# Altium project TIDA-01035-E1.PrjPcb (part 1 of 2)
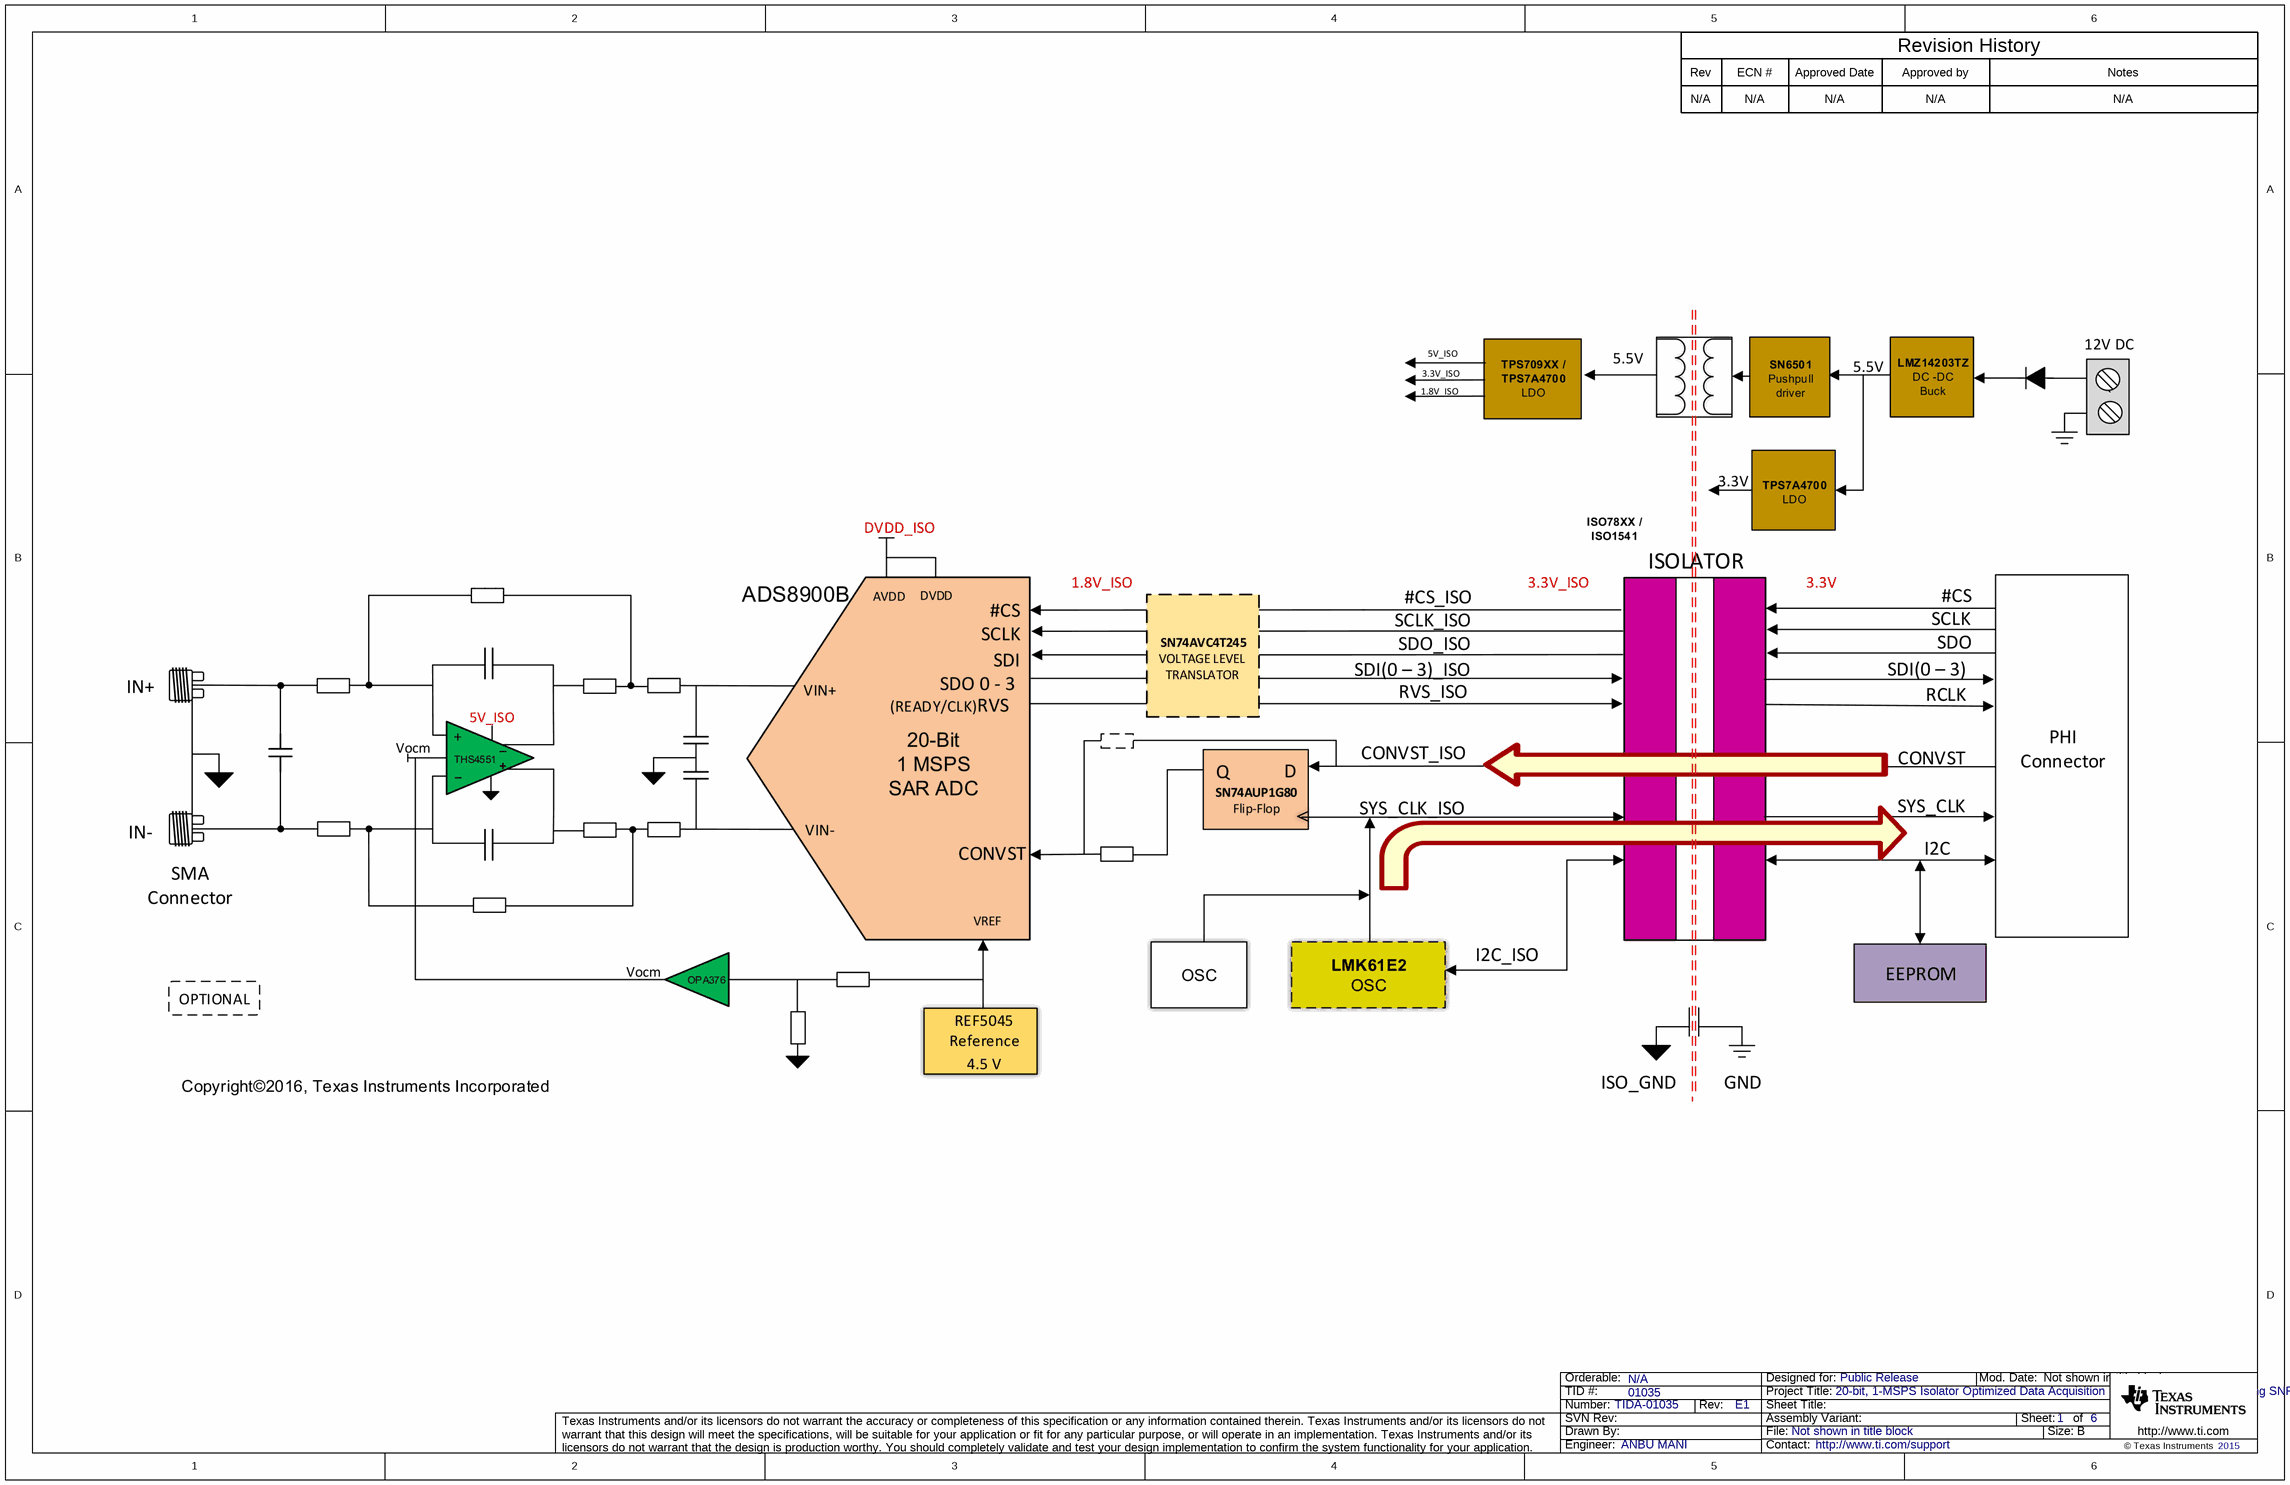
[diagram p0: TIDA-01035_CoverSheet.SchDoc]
CopyrightYear: 2015; EVM_Orderable: N/A; PCB_Layout: Avinash N; PCB_Rev: E1; PRJ_Customer: Public Release; PRJ_Engineer: ANBU MANI; PRJ_Number: TIDA-01035; PRJ_Title: 20-bit, 1-MSPS Isolator Optimized Data Acquisition Reference Design Maximizing SNR and Sample Rate; SCH_Rev: E1; TechSupport: http://www.ti.com/support; TID: 01035
6 sheets, 287 parts. Net scope: flat (ports and power ports of the same name join across sheets).
Board file: TIDA-01035.PcbDoc
Sheets:
  TIDA-01035_CoverSheet.SchDoc
  TIDA-01035_CONNECTOR.SchDoc
  TIDA-01035_POWER_ISOLATION.SchDoc
  TIDA-01035_DATA_ISOLATION.SchDoc
  TIDA-01035_ADC1.SchDoc
  TIDA-01035_Hardware.SchDoc

## Sheet TIDA-01035_CoverSheet.SchDoc
size 431 x 279 mm; Date: Not shown in title block; ApprovedBy: Not shown in title block; CheckedBy: Not shown in title block; Author: Not shown in title block; CompanyName: Not shown in title block; Engineer: Not shown in title block; Organization: Not shown in title block; Address1: Not shown in title block; Address2: Not shown in title block; Address3: Not shown in title block; Address4: Not shown in title block; DocumentNumber: 1; Revision: Use project parameter SCH_Rev; SheetNumber: 1; SheetTotal: 6; PageSetup: Record=PageOptions¦CenterHorizontal=True¦CenterVertical=True¦PrintScale=1.00¦XCorrection=1.00¦YCorrection=1.00¦PrintKind=0¦BorderSize=5000000¦LeftOffset=0¦BottomOffset=0¦Orientation=2¦PaperLength=1000¦PaperWidth=1000¦Scale=100¦PaperSource=15¦PrintQuality=600¦MediaType=1¦DitherType=10¦PrintScaleMode=1¦PaperKind=Letter

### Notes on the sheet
- Rev
- N/A
- ECN #
- Approved Date
- Approved by
- Revision History
- Notes

## Sheet TIDA-01035_CONNECTOR.SchDoc
size 431 x 279 mm; Date: Not shown in title block; ApprovedBy: Not shown in title block; CheckedBy: Not shown in title block; Author: Not shown in title block; CompanyName: Not shown in title block; Engineer: Not shown in title block; Organization: Not shown in title block; Address1: Not shown in title block; Address2: Not shown in title block; Address3: Not shown in title block; Address4: Not shown in title block; DocumentNumber: 1; Revision: Use project parameter SCH_Rev; SheetNumber: 2; SheetTotal: 6; PageSetup: Record=PageOptions¦CenterHorizontal=True¦CenterVertical=True¦PrintScale=1.00¦XCorrection=1.00¦YCorrection=1.00¦PrintKind=0¦BorderSize=5000000¦LeftOffset=0¦BottomOffset=0¦Orientation=2¦PaperLength=1000¦PaperWidth=1000¦Scale=100¦PaperSource=15¦PrintQuality=600¦MediaType=1¦DitherType=10¦PaperKind=Letter¦PrintScaleMode=1
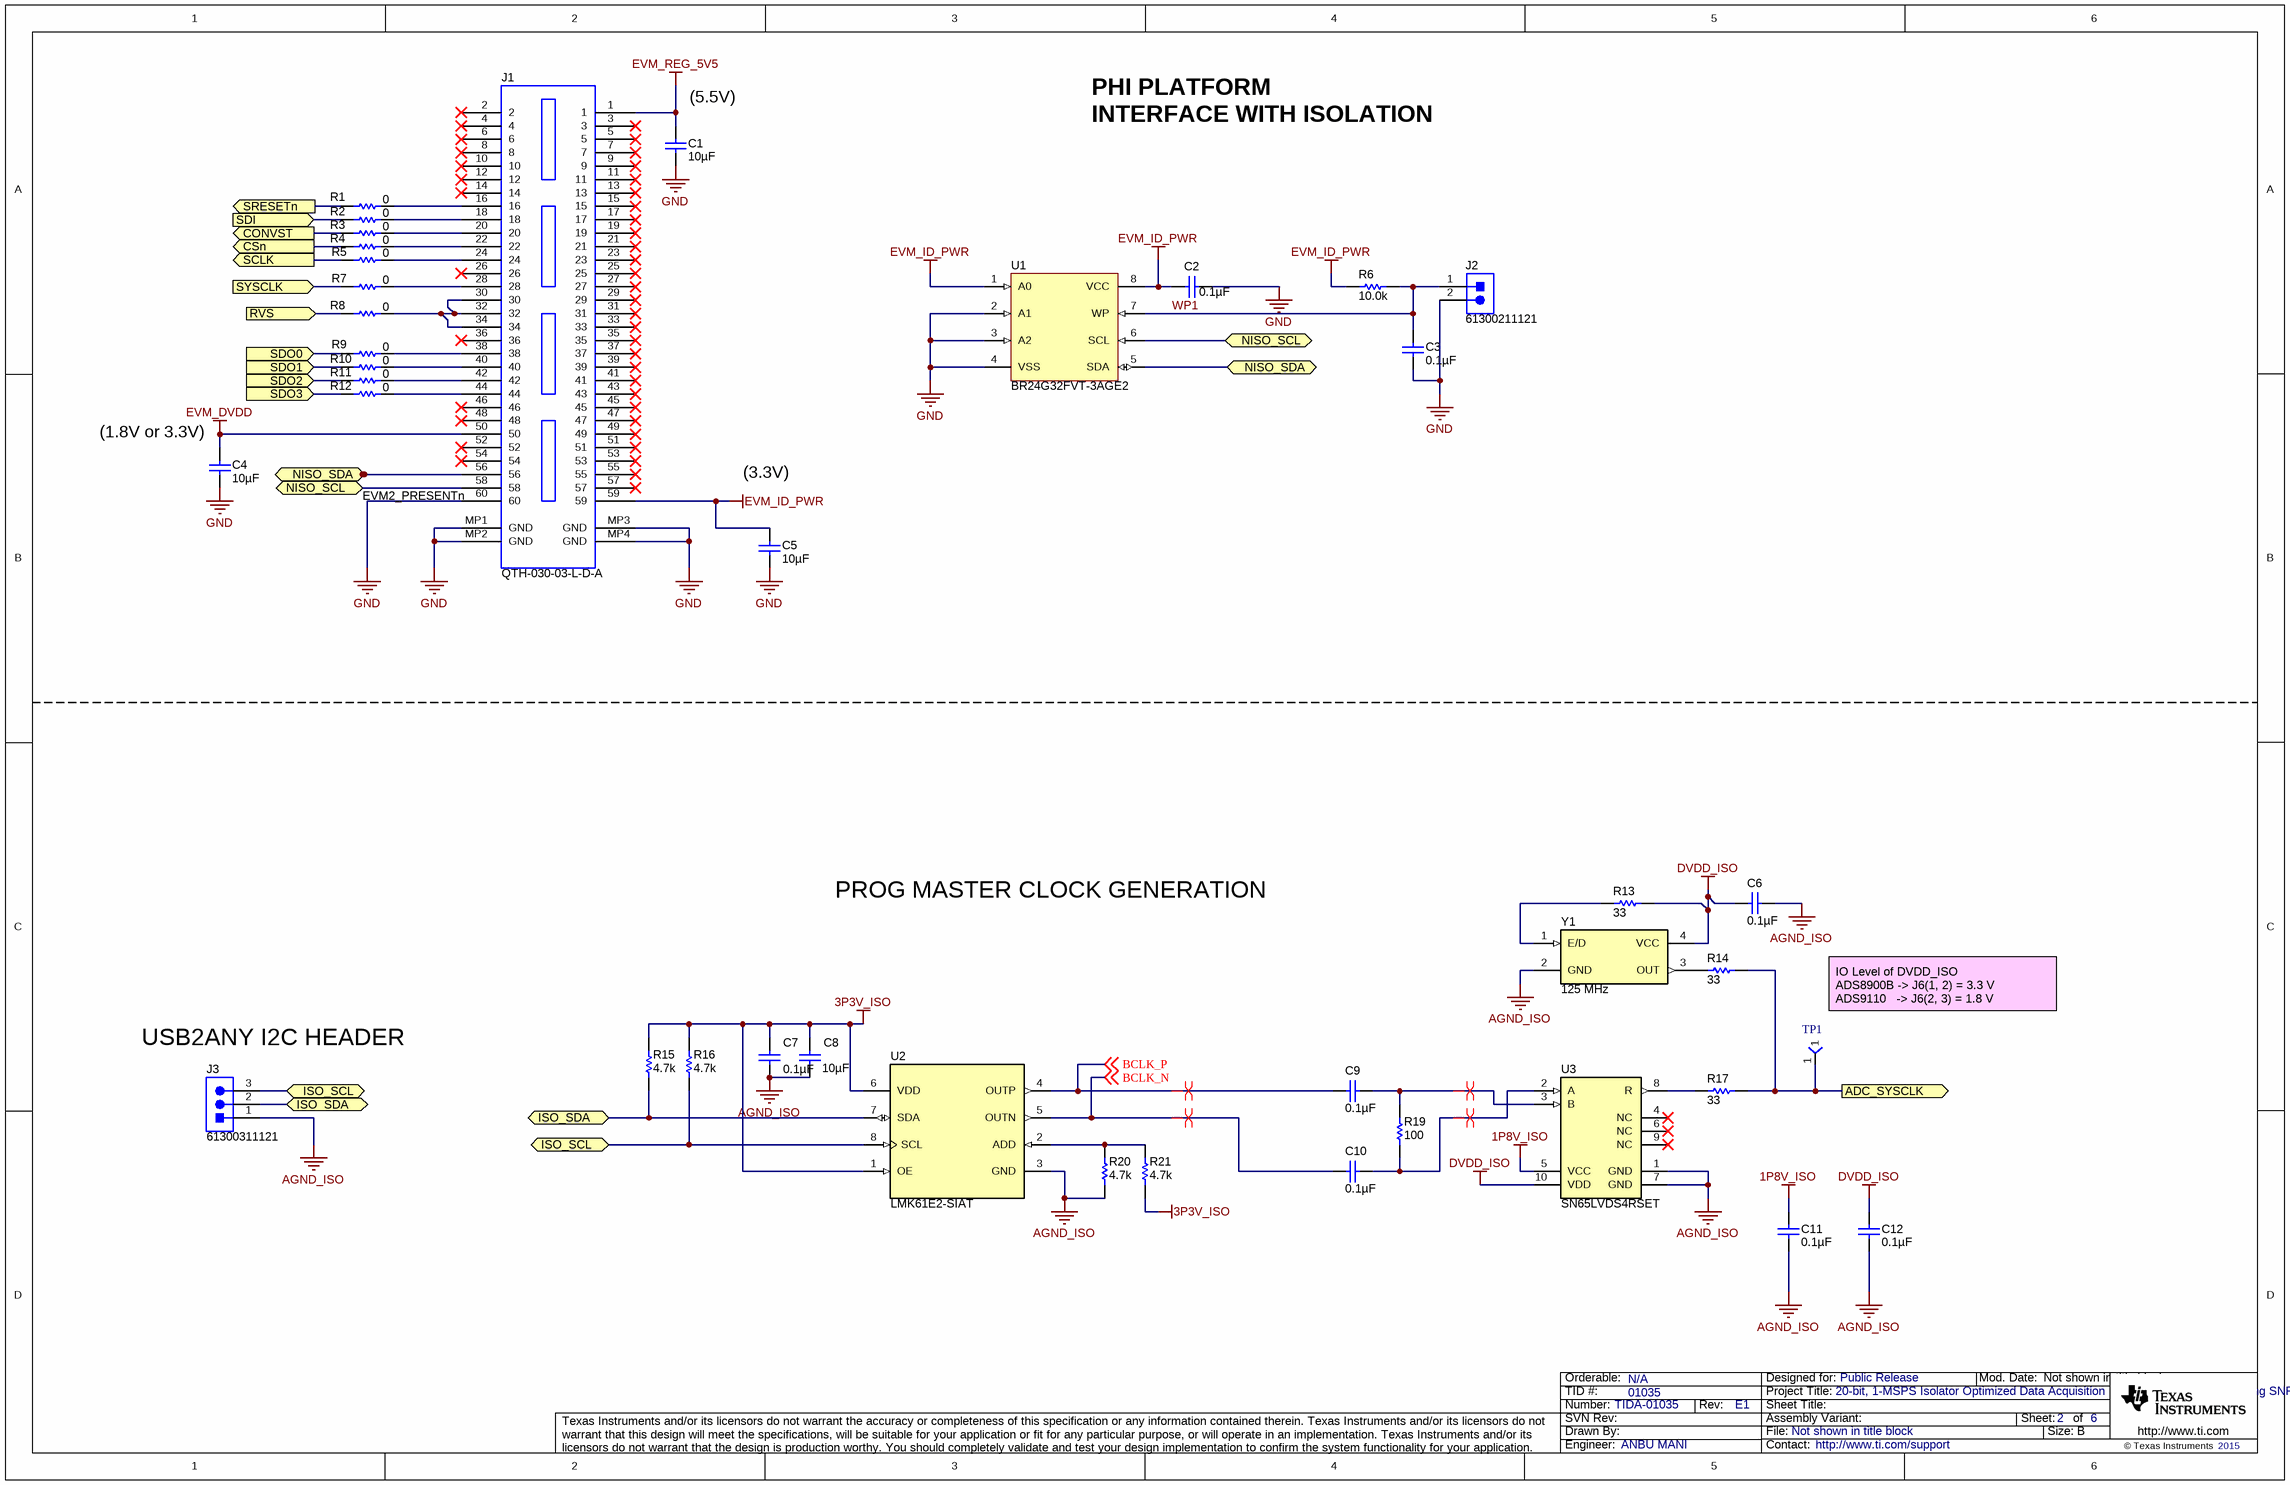
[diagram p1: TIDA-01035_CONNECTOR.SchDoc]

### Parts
C1  ValueDisplayed: 10µF  [0805_HV]  (hidden comment: GRM21BR71A106KE51L)
C2  ValueDisplayed: 0.1µF  [0402]  (hidden comment: GRM155R71C104KA88D)
C3  ValueDisplayed: 0.1µF  [0402]  (hidden comment: GRM155R71C104KA88D)
C4  ValueDisplayed: 10µF  [0805_HV]  (hidden comment: GRM21BR71A106KE51L)
C5  ValueDisplayed: 10µF  [0805_HV]  (hidden comment: GRM21BR71A106KE51L)
C6  ValueDisplayed: 0.1µF  [0402]  (hidden comment: GRM155R71C104KA88D)
C7  ValueDisplayed: 0.1µF  [0603]  (hidden comment: C0603C104J3RACTU)
C8  ValueDisplayed: 10µF  [0603_120]  (hidden comment: ZRB18AD71A106KE01L)
C9  ValueDisplayed: 0.1µF  [0402]  (hidden comment: GRM155R61E104KA87D)
C10  ValueDisplayed: 0.1µF  [0402]  (hidden comment: GRM155R61E104KA87D)
C11  ValueDisplayed: 0.1µF  [0402]  (hidden comment: GRM155R71C104KA88D)
C12  ValueDisplayed: 0.1µF  [0402]  (hidden comment: GRM155R71C104KA88D)
J1  QTH-030-03-L-D-A  [Samtec_QTH-030-01-x-D-A]
J2  61300211121  [WURTH_61300211121]
J3  61300311121  [WURTH_61300311121]
R1  ValueDisplayed: 0  [0402]  (hidden comment: ERJ-2GE0R00X)
R2  ValueDisplayed: 0  [0402]  (hidden comment: ERJ-2GE0R00X)
R3  ValueDisplayed: 0  [0402]  (hidden comment: ERJ-2GE0R00X)
R4  ValueDisplayed: 0  [0402]  (hidden comment: ERJ-2GE0R00X)
R5  ValueDisplayed: 0  [0402]  (hidden comment: ERJ-2GE0R00X)
R6  ValueDisplayed: 10.0k  [0603]  (hidden comment: CRCW060310K0FKEA)
R7  ValueDisplayed: 0  [0402]  (hidden comment: ERJ-2GE0R00X)
R8  ValueDisplayed: 0  [0402]  (hidden comment: ERJ-2GE0R00X)
R9  ValueDisplayed: 0  [0402]  (hidden comment: ERJ-2GE0R00X)
R10  ValueDisplayed: 0  [0402]  (hidden comment: ERJ-2GE0R00X)
R11  ValueDisplayed: 0  [0402]  (hidden comment: ERJ-2GE0R00X)
R12  ValueDisplayed: 0  [0402]  (hidden comment: ERJ-2GE0R00X)
R13  ValueDisplayed: 33  [0402]  (hidden comment: CRCW040233R0JNED)
R14  ValueDisplayed: 33  [0402]  (hidden comment: CRCW040233R0JNED)
R15  ValueDisplayed: 4.7k  [0402]  (hidden comment: CRCW04024K70JNED)
R16  ValueDisplayed: 4.7k  [0402]  (hidden comment: CRCW04024K70JNED)
R17  ValueDisplayed: 33  [0402]  (hidden comment: CRCW040233R0JNED)
R19  ValueDisplayed: 100  [0402]  (hidden comment: RC0402FR-07100RL)
R20  ValueDisplayed: 4.7k  [0402]  (hidden comment: CRCW04024K70JNED)
R21  ValueDisplayed: 4.7k  [0402]  (hidden comment: CRCW04024K70JNED)
TP1  TP-025-SMT  [TP_25MIL-SMT]  (value not drawn)
U1  BR24G32FVT-3AGE2  [TSOP65P640X120-8N]
U2  LMK61E2-SIAT  [SIA0008B]
U3  SN65LVDS4RSET  [RSE0010A]
Y1  Frequency: 125 MHz  [TXC_AU]  (hidden comment: ASTMLPE-125.000MHZ-LJ-E-T)

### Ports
ADC_SYSCLK (out), CONVST (out), CSn (out), ISO_SCL (bidir), ISO_SDA (bidir), NISO_SCL (bidir), NISO_SDA (bidir), RVS (in), SCLK (out), SDI (in), SDO0 (in), SDO1 (in), SDO2 (in), SDO3 (in), SRESETn (out), SYSCLK (in)

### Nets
1P8V_ISO: C11.1 U3.5(VCC)
3P3V_ISO: C7.1 C8.1 R15.2 R16.2 R21.1 U2.1(OE) U2.6(VDD)
AGND_ISO: C6.2 C7.2 C8.2 C11.2 C12.2 J3.1 R20.1 U2.3(GND) U3.1(GND) U3.7(GND) Y1.2(GND)
DVDD_ISO: C6.1 C12.1 R13.2 U3.10(VDD) Y1.4(VCC)
EVM_DVDD: C4.1 J1.50
EVM_ID_PWR: C2.2 C5.1 J1.59 R6.2 U1.1(A0) U1.8(VCC)
EVM_REG_5V5: C1.1 J1.1
GND: C1.2 C2.1 C3.1 C4.2 C5.2 J1.60 J1.MP1(GND) J1.MP2(GND) J1.MP3(GND) J1.MP4(GND) J2.2 U1.2(A1) U1.3(A2) U1.4(VSS)
ADC_SYSCLK: R14.2 R17.2 TP1.1 ; port ADC_SYSCLK
BCLK_N: C10.1 U2.5(OUTN) ; off-sheet BCLK_N
BCLK_P: C9.1 U2.4(OUTP) ; off-sheet BCLK_P
CONVST: R3.1 ; port CONVST
CSn: R4.1 ; port CSn
ISO_SCL: J3.3 R16.1 U2.8(SCL) ; port ISO_SCL
ISO_SDA: J3.2 R15.1 U2.7(SDA) ; port ISO_SDA
NISO_SCL: J1.58 U1.6(SCL) ; port NISO_SCL
NISO_SDA: J1.56 U1.5(SDA) ; port NISO_SDA
RVS: R8.1 ; port RVS
SCLK: R5.1 ; port SCLK
SDI: R2.1 ; port SDI
SDO0: R9.1 ; port SDO0
SDO1: R10.1 ; port SDO1
SDO2: R11.1 ; port SDO2
SDO3: R12.1 ; port SDO3
SRESETn: R1.1 ; port SRESETn
SYSCLK: R7.1 ; port SYSCLK
WP1: C3.2 J2.1 R6.1 U1.7(WP)
NetC9_2: C9.2 R19.2 U3.3(B)
NetC10_2: C10.2 R19.1 U3.2(A)
NetJ1_16: J1.16 R1.2
NetJ1_18: J1.18 R2.2
NetJ1_20: J1.20 R3.2
NetJ1_22: J1.22 R4.2
NetJ1_24: J1.24 R5.2
NetJ1_28: J1.28 R7.2
NetJ1_30: J1.30 J1.32 J1.34 R8.2
NetJ1_38: J1.38 R9.2
NetJ1_40: J1.40 R10.2
NetJ1_42: J1.42 R11.2
NetJ1_44: J1.44 R12.2
NetR13_1: R13.1 Y1.1(E/D)
NetR14_1: R14.1 Y1.3(OUT)
NetR17_1: R17.1 U3.8(R)
NetR20_2: R20.2 R21.2 U2.2(ADD)

Not connected (* = marked no-connect by the designer): J1 2* 3* 4* 5* 6* 7* 8* 9* 10* 11* 12* 13* 14* 15* 17* 19* 21* 23* 25* 26* 27* 29* 31* 33* 35* 36* 37* 39* 41* 43* 45* 46* 47* 48* 49* 51* 52* 53* 54* 55* 57*; U3 4(NC)* 6(NC)* 9(NC)*

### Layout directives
differential pair: BCLK_N, BCLK_P, NetC9_2, NetC10_2

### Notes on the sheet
- (near C1) (5.5V)
- PHI PLATFORM
  INTERFACE WITH ISOLATION
- (near C4) (1.8V or 3.3V)
- (near J1) EVM2_PRESENTn
- (3.3V)
- PROG MASTER CLOCK GENERATION
- (near J3) USB2ANY I2C HEADER
- (near TP1) IO Level of DVDD_ISO
  ADS8900B -> J6(1, 2) = 3.3 V
  ADS9110   -> J6(2, 3) = 1.8 V

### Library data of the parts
C1 C4 C5 = GRM21BR71A106KE51L: CAP, CERM, 10 µF, 10 V, +/- 10%, X7R, 0805; Manufacturer: MuRata; Polarized: N; CompType: Capacitor; Value: 10uF; U/M: EA; Cap_F: 0.00001; Tolerance_%: 10; ESR_ohm: 0.003; Value1: 0.003 ohm; Value2: 10V; TaMin_C: -55; TaMax_C: 125; Cap_Case: 0805; AEC Category: Q200
C2 C3 C6 C11 C12 = GRM155R71C104KA88D: CAP, CERM, 0.1 µF, 16 V, +/- 10%, X7R, 0402; Manufacturer: MuRata; Polarized: N; CompType: Capacitor; Value: 0.1uF; U/M: EA; Cap_F: 0.0000001; Tolerance_%: 10; Value1: Unknown; VDC_V: 16; Value2: 16V; TaMin_C: -55; TaMax_C: 125
C7 = C0603C104J3RACTU: CAP, CERM, 0.1 µF, 25 V, +/- 5%, X7R, 0603; Manufacturer: Kemet; Polarized: N; CompType: Capacitor; Value: 0.1uF; U/M: EA; Cap_F: 0.0000001; Tolerance_%: 5; Value1: Unknown; VDC_V: 25; Value2: 25V; TaMin_C: -55; TaMax_C: 125
C8 = ZRB18AD71A106KE01L: CAP, CERM, 10 µF, 10 V, +/- 10%, X7T, 0603; Manufacturer: MuRata; Polarized: N; CompType: Capacitor; Value: 10uF; U/M: EA; Cap_F: 0.00001; Tolerance_%: 10; Value1: Unknown; Value2: 10V; TaMin_C: -55; TaMax_C: 125; Cap_Case: 0603; AEC Category: Q200
C9 C10 = GRM155R61E104KA87D: CAP, CERM, 0.1 µF, 25 V, +/- 10%, X5R, 0402; Manufacturer: MuRata; Polarized: N; CompType: Capacitor; Value: 0.1uF; U/M: EA; Cap_F: 0.0000001; Tolerance_%: 10; Value1: Unknown; VDC_V: 25; Value2: 25V; TaMin_C: -55; TaMax_C: 85; AEC Category: Q200
J1 = QTH-030-01-L-D-A: Header(Shrouded), 19.7mil, 30x2, Gold, SMT; Manufacturer: Samtec; SymbolCreator: Altium; U/M: EA
J2 = 61300211121: Header, 2.54 mm, 2x1, Gold, TH; Manufacturer: Wurth Elektronik eiSos; SymbolCreator: a0412235; U/M: EA
J3 = 61300311121: Header, 2.54 mm, 3x1, Gold, TH; Manufacturer: Wurth Elektronik eiSos; SymbolCreator: a0799628; U/M: EA
R1-R5 R7-R12 = ERJ-2GE0R00X: RES, 0, 5%, 0.063 W, 0402; Manufacturer: Panasonic; CompType: Resistor; Value: 0; Value_Code: 0000; Tolerance_%: 5; Power_W: 0.063; Value2: 0.063W; VDC_V: 50; TempCo: 600 ppm/C; EIA_Code: E24; U/M: EA; AEC Category: Q200
R6 = CRCW060310K0FKEA: RES, 10.0 k, 1%, 0.1 W, 0603; Manufacturer: Vishay-Dale; CompType: Resistor; Value: 10.0k; Res_ohm: 10000; Value_Code: 10k0; Tolerance_%: 1; Power_W: 0.1; Value2: 0.1W; VDC_V: 75; TempCo: 100 ppm/C; EIA_Code: E96; U/M: EA
R13 R14 R17 = CRCW040233R0JNED: RES, 33, 5%, 0.063 W, 0402; Manufacturer: Vishay-Dale; CompType: Resistor; Value: 33; Value_Code: 33R0; Tolerance_%: 5; Power_W: 0.063; Value2: 0.063W; VDC_V: 50; TempCo: 200 ppm/C; EIA_Code: E24; U/M: EA; AEC Category: Q200
R15 R16 R20 R21 = CRCW04024K70JNED: RES, 4.7 k, 5%, 0.063 W, 0402; Manufacturer: Vishay-Dale; CompType: Resistor; Value: 4.7k; Res_ohm: 4700; Value_Code: 4k70; Tolerance_%: 5; Power_W: 0.063; Value2: 0.063W; VDC_V: 50; TempCo: 200 ppm/C; EIA_Code: E24; U/M: EA; AEC Category: Q200
R19 = RC0402FR-07100RL: RES, 100, 1%, 0.063 W, 0402; Manufacturer: Yageo America; CompType: Resistor; Value: 100; Value_Code: 100R; Tolerance_%: 1; Power_W: 0.063; Value2: 0.063W; VDC_V: 50; TempCo: 100 ppm/C; EIA_Code: E96; U/M: EA; AEC Category: Q200; AEC Qualified: N; SizeArea_mm2: 0.5; SizeZ_mm: 0.6
TP1 = TP-025-SMT: Test Point, O.025"; Manufacturer: STD; Value: STD
U1 = BR24G32FVT-3AGE2: I2C BUS EEPROM (2-Wire), TSSOP-B8; Manufacturer: Rohm; SymbolCreator: a0411947
U2 = LMK61E2-SIAR: Ultra-Low Jitter Programmable Oscillator with Internal EEPROM, SIA0008B; Manufacturer: Texas Instruments; SymbolCreator: Altium; CompType: IC; U/M: EA
U3 = SN65LVDS4RSET: 500 Mbps High-Speed Differential Line Driver / Receivers with LVDS Input and LVTTL / LVCMOS Output, 1 Rx, -40 to +85 degC, 10-pin UQFN (RSE), Green (RoHS & no Sb/Br); Manufacturer: Texas Instruments; Alternate PartNumber: Equivalent; ESD HBM(kV): 2; Function: Transceiver; No. of Rx: 1; No. of Tx: 0; Output Signal: LVTTL, LVCMOS; Signaling Rate(Mbps): 500; SubFamily: LVDS PHY (<800Mbps)
Y1 = AU-40.000MDE-T: OSC, 125 MHz, 3.3V, SMD; Manufacturer: ABRACON; SymbolCreator: a0411947; CompType: Oscillator; U/M: EA; TaMin_C: -40; TaMax_C: 85; Frequency Stability: ±50ppm

## Sheet TIDA-01035_POWER_ISOLATION.SchDoc: LDO's Isolated & Non Isolated
size 431 x 279 mm; Date: Not shown in title block; ApprovedBy: Not shown in title block; CheckedBy: Not shown in title block; Author: Not shown in title block; CompanyName: Not shown in title block; DrawnBy: Anbu Mani; Engineer: Not shown in title block; Organization: Not shown in title block; Address1: Not shown in title block; Address2: Not shown in title block; Address3: Not shown in title block; Address4: Not shown in title block; DocumentNumber: 1; Revision: Use project parameter SCH_Rev; SheetNumber: 3; SheetTotal: 6; PageSetup: Record=PageOptions¦CenterHorizontal=True¦CenterVertical=True¦PrintScale=1.00¦XCorrection=1.00¦YCorrection=1.00¦PrintKind=0¦BorderSize=5000000¦LeftOffset=0¦BottomOffset=0¦Orientation=2¦PaperLength=1000¦PaperWidth=1000¦Scale=100¦PaperSource=15¦PrintQuality=600¦MediaType=1¦DitherType=10¦PaperKind=Letter¦PrintScaleMode=1
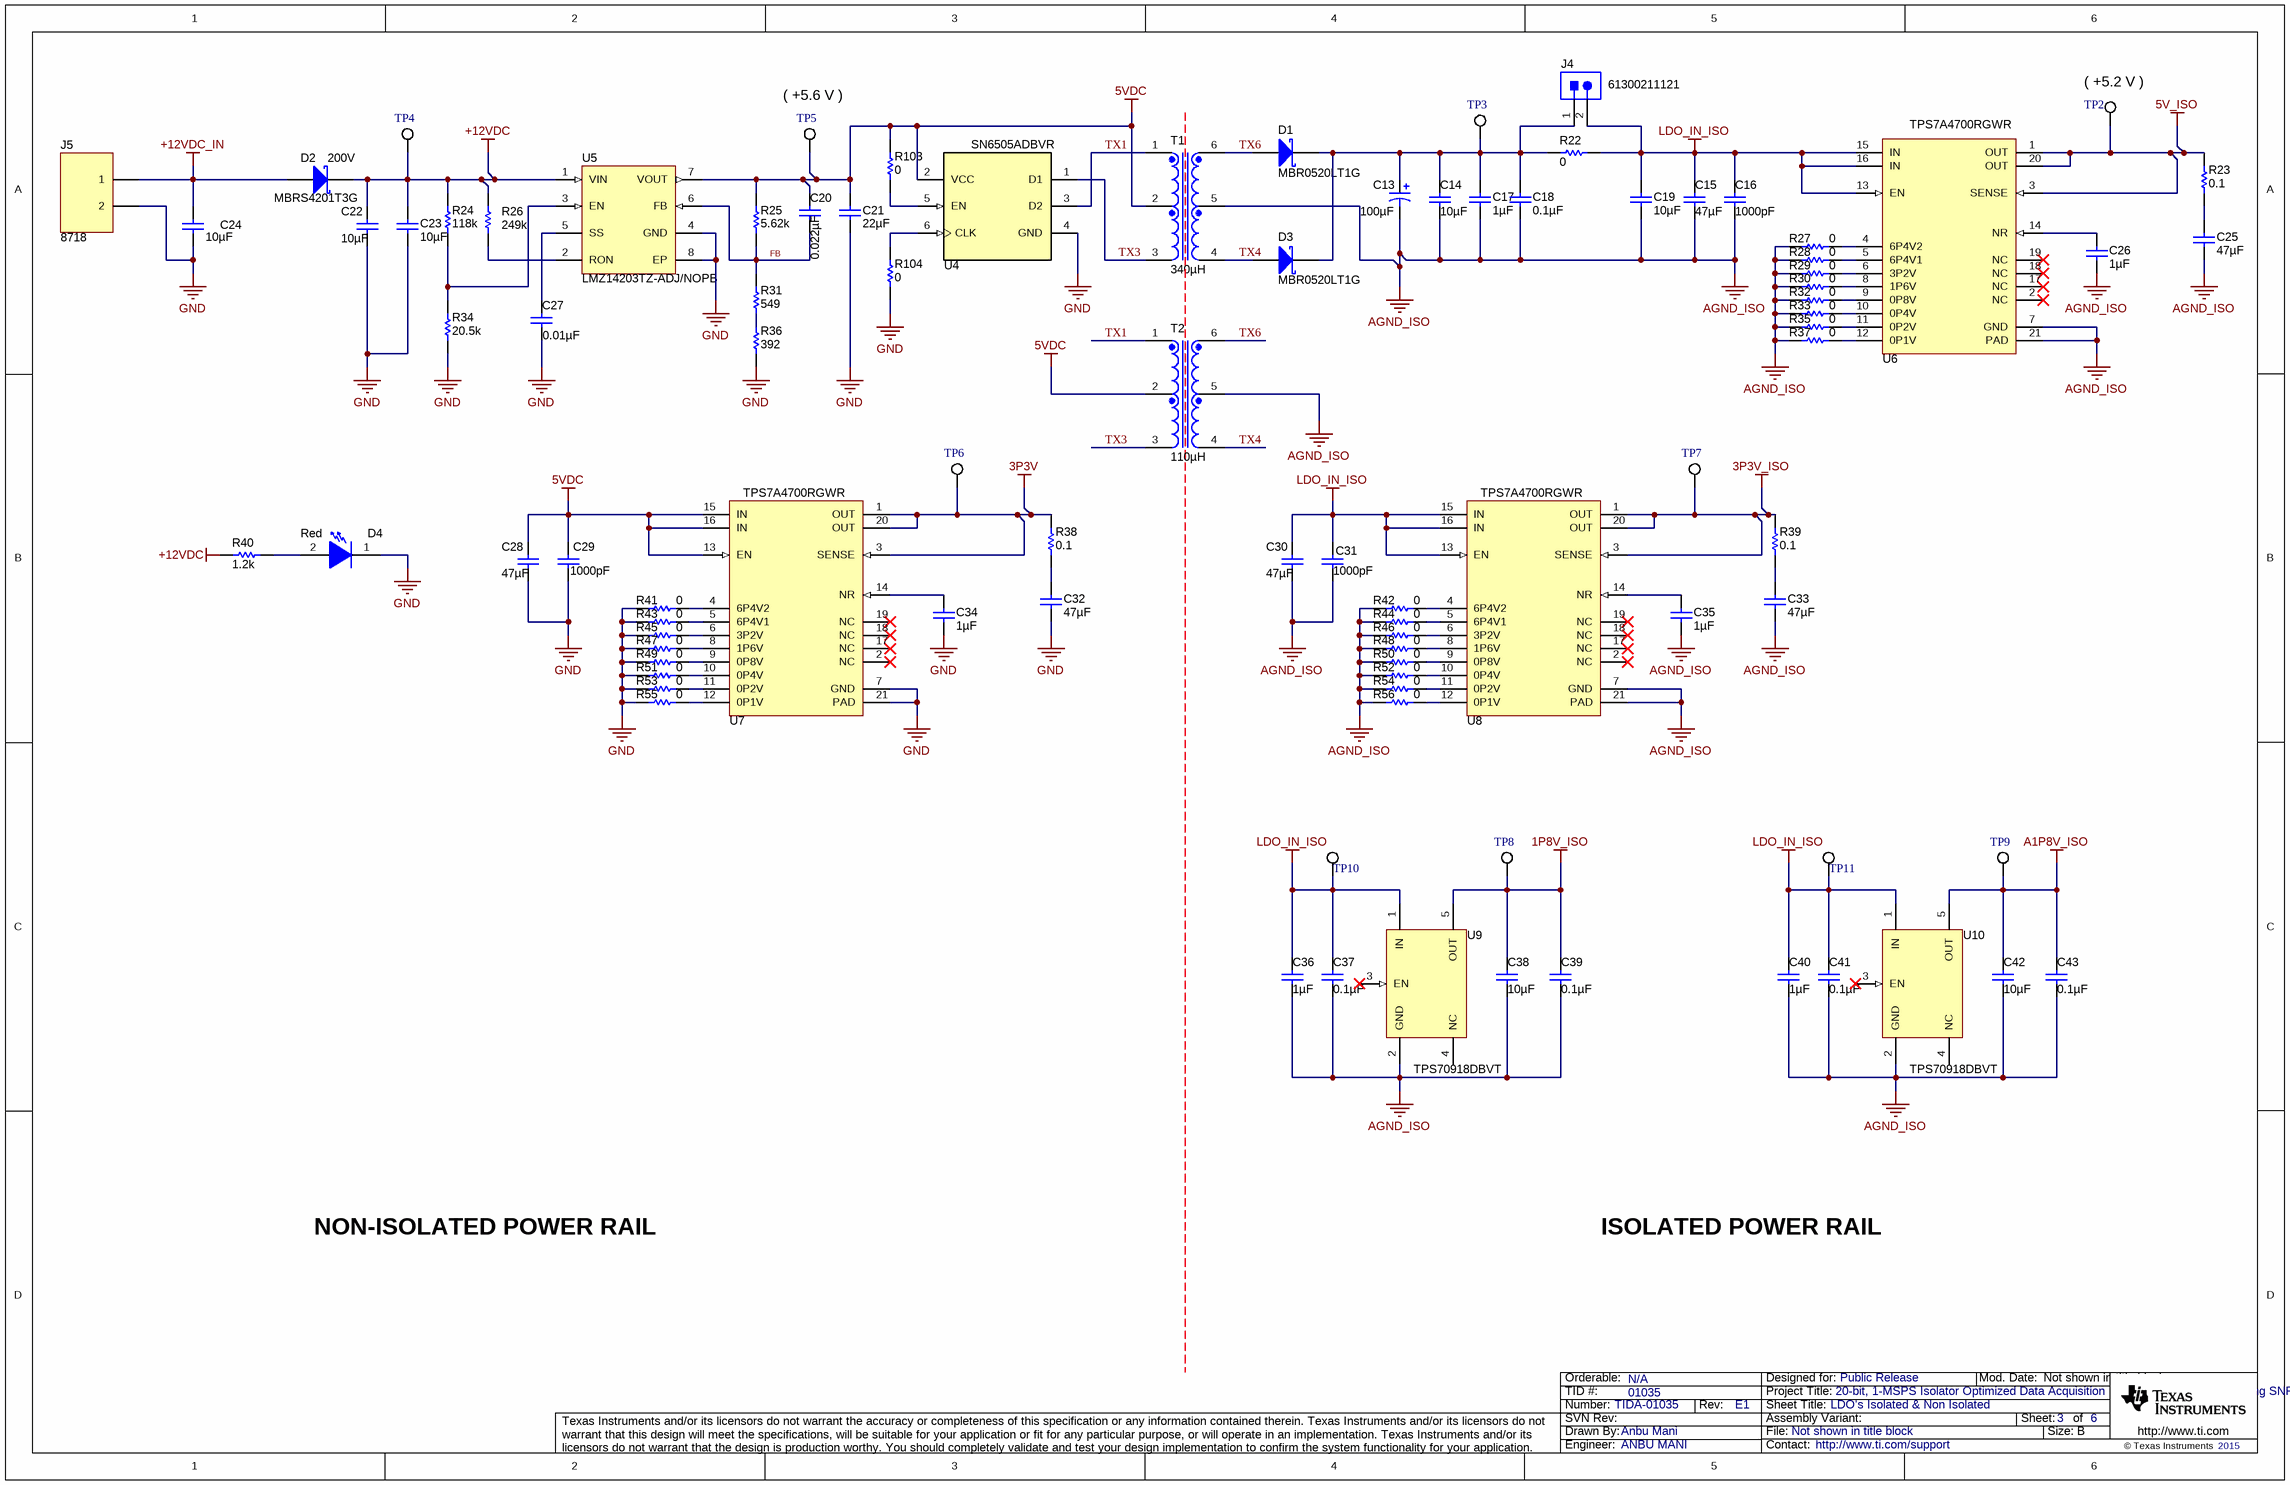
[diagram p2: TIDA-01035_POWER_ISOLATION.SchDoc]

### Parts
C13  ValueDisplayed: 100µF  [7343-43]  (hidden comment: TPME107K020R0035)
C14  ValueDisplayed: 10µF  [1206_190]  (hidden comment: C3216X7R1E106M160AE)
C15  ValueDisplayed: 47µF  [1206_190]  (hidden comment: C3216X5R1E476M160AC)
C16  ValueDisplayed: 1000pF  [0603]  (hidden comment: GRM1885C1H102FA01J)
C17  ValueDisplayed: 1µF  [0603]  (hidden comment: GRM188R71E105KA12D)
C18  ValueDisplayed: 0.1µF  [0402]  (hidden comment: GRM155R71C104KA88D)
C19  ValueDisplayed: 10µF  [0805_HV]  (hidden comment: GRM21BR71A106KE51L)
C20  ValueDisplayed: 0.022µF  [0805_HV]  (hidden comment: 08055C223KAT2A)
C21  ValueDisplayed: 22µF  [1210]  (hidden comment: C3225X5R1A226M230AA)
C22  ValueDisplayed: 10µF  [1210_280]  (hidden comment: C1210C106K5RACTU)
C23  ValueDisplayed: 10µF  [1210_280]  (hidden comment: C1210C106K5RACTU)
C24  ValueDisplayed: 10µF  [1206_190]  (hidden comment: C3216X7R1E106M160AE)
C25  ValueDisplayed: 47µF  [1206_190]  (hidden comment: C3216X5R1E476M160AC)
C26  ValueDisplayed: 1µF  [0603]  (hidden comment: GRM188R71E105KA12D)
C27  ValueDisplayed: 0.01µF  [0603]  (hidden comment: C0603C103J5RACTU)
C28  ValueDisplayed: 47µF  [1206_190]  (hidden comment: C3216X5R1E476M160AC)
C29  ValueDisplayed: 1000pF  [0603]  (hidden comment: GRM1885C1H102FA01J)
C30  ValueDisplayed: 47µF  [1206_190]  (hidden comment: C3216X5R1E476M160AC)
C31  ValueDisplayed: 1000pF  [0603]  (hidden comment: GRM1885C1H102FA01J)
C32  ValueDisplayed: 47µF  [1206_190]  (hidden comment: C3216X5R1E476M160AC)
C33  ValueDisplayed: 47µF  [1206_190]  (hidden comment: C3216X5R1E476M160AC)
C34  ValueDisplayed: 1µF  [0603]  (hidden comment: GRM188R71E105KA12D)
C35  ValueDisplayed: 1µF  [0603]  (hidden comment: GRM188R71E105KA12D)
C36  ValueDisplayed: 1µF  [0805]  (hidden comment: 08055C105KAT2A)
C37  ValueDisplayed: 0.1µF  [0603]  (hidden comment: C0603C104K5RACTU)
C38  ValueDisplayed: 10µF  [0805]  (hidden comment: 0805YD106MAT2A)
C39  ValueDisplayed: 0.1µF  [0603]  (hidden comment: C0603C104K5RACTU)
C40  ValueDisplayed: 1µF  [0805]  (hidden comment: 08055C105KAT2A)
C41  ValueDisplayed: 0.1µF  [0603]  (hidden comment: C0603C104K5RACTU)
C42  ValueDisplayed: 10µF  [0805]  (hidden comment: 0805YD106MAT2A)
C43  ValueDisplayed: 0.1µF  [0603]  (hidden comment: C0603C104K5RACTU)
D1  MBR0520LT1G  [SOD-123]
D2  value 200V  [SMC]  (hidden comment: MBRS4201T3G)
D3  MBR0520LT1G  [SOD-123]
D4  value Red  [WL-SMCW_RED]  (hidden comment: 150060RS75000)
J4  61300211121  [WURTH_61300211121]
J5  8718  [691213510002]
R22  ValueDisplayed: 0  [1206]  (hidden comment: CRCW12060000Z0EA)
R23  ValueDisplayed: 0.1  [0603]  (hidden comment: ERJ-3RSFR10V)
R24  ValueDisplayed: 118k  [0805_HV]  (hidden comment: ERJ-6ENF1183V)
R25  ValueDisplayed: 5.62k  [0805_HV]  (hidden comment: RC0805FR-075K62L)
R26  value 249k  [0805_HV]  (hidden comment: CRCW0805249KFKEA)
R27  ValueDisplayed: 0  [0402]  (hidden comment: ERJ-2GE0R00X)
R28  ValueDisplayed: 0  [0402]  (hidden comment: ERJ-2GE0R00X)
R29  ValueDisplayed: 0  [0402]  (hidden comment: ERJ-2GE0R00X)
R30  ValueDisplayed: 0  [0402]  (hidden comment: ERJ-2GE0R00X)
R31  ValueDisplayed: 549  [0805_HV]  (hidden comment: RR1220P-5490-D-M)
R32  ValueDisplayed: 0  [0402]  (hidden comment: ERJ-2GE0R00X)
R33  ValueDisplayed: 0  [0402]  (hidden comment: ERJ-2GE0R00X)
R34  ValueDisplayed: 20.5k  [0805_HV]  (hidden comment: CRCW080520K5FKEA)
R35  ValueDisplayed: 0  [0402]  (hidden comment: ERJ-2GE0R00X)
R36  ValueDisplayed: 392  [0805_HV]  (hidden comment: RR1220P-3920-D-M)
R37  ValueDisplayed: 0  [0402]  (hidden comment: ERJ-2GE0R00X)
R38  ValueDisplayed: 0.1  [0603]  (hidden comment: ERJ-3RSFR10V)
R39  ValueDisplayed: 0.1  [0603]  (hidden comment: ERJ-3RSFR10V)
R40  ValueDisplayed: 1.2k  [0603]  (hidden comment: CRCW06031K20JNEA)
R41  ValueDisplayed: 0  [0402]  (hidden comment: ERJ-2GE0R00X)
R42  ValueDisplayed: 0  [0402]  (hidden comment: ERJ-2GE0R00X)
R43  ValueDisplayed: 0  [0402]  (hidden comment: ERJ-2GE0R00X)
R44  ValueDisplayed: 0  [0402]  (hidden comment: ERJ-2GE0R00X)
R45  ValueDisplayed: 0  [0402]  (hidden comment: ERJ-2GE0R00X)
R46  ValueDisplayed: 0  [0402]  (hidden comment: ERJ-2GE0R00X)
R47  ValueDisplayed: 0  [0402]  (hidden comment: ERJ-2GE0R00X)
R48  ValueDisplayed: 0  [0402]  (hidden comment: ERJ-2GE0R00X)
R49  ValueDisplayed: 0  [0402]  (hidden comment: ERJ-2GE0R00X)
R50  ValueDisplayed: 0  [0402]  (hidden comment: ERJ-2GE0R00X)
R51  ValueDisplayed: 0  [0402]  (hidden comment: ERJ-2GE0R00X)
R52  ValueDisplayed: 0  [0402]  (hidden comment: ERJ-2GE0R00X)
R53  ValueDisplayed: 0  [0402]  (hidden comment: ERJ-2GE0R00X)
R54  ValueDisplayed: 0  [0402]  (hidden comment: ERJ-2GE0R00X)
R55  ValueDisplayed: 0  [0402]  (hidden comment: ERJ-2GE0R00X)
R56  ValueDisplayed: 0  [0402]  (hidden comment: ERJ-2GE0R00X)
R103  ValueDisplayed: 0  [0603]  (hidden comment: CRCW06030000Z0EA)
R104  ValueDisplayed: 0  [0603]  (hidden comment: CRCW06030000Z0EA)
T1  ValueDisplayed: 340µH  [Wurth_750313638]  (hidden comment: 750313734)
T2  ValueDisplayed: 110µH  [Wurth_750315240]  (hidden comment: 750315240)
TP2  5015  [Testpoint_Keystone_Miniature]  (value not drawn)
TP3  5015  [Testpoint_Keystone_Miniature]  (value not drawn)
TP4  5015  [Testpoint_Keystone_Miniature]  (value not drawn)
TP5  5015  [Testpoint_Keystone_Miniature]  (value not drawn)
TP6  5015  [Testpoint_Keystone_Miniature]  (value not drawn)
TP7  5015  [Testpoint_Keystone_Miniature]  (value not drawn)
TP8  5015  [Testpoint_Keystone_Miniature]  (value not drawn)
TP9  5015  [Testpoint_Keystone_Miniature]  (value not drawn)
TP10  5015  [Testpoint_Keystone_Miniature]  (value not drawn)
TP11  5015  [Testpoint_Keystone_Miniature]  (value not drawn)
U4  SN6505ADBVR  [DBV0006A_N]
U5  LMZ14203TZ-ADJ/NOPB  [TZA07A_V]
U6  TPS7A4700RGWR  [RGW0020A]
U7  TPS7A4700RGWR  [RGW0020A]
U8  TPS7A4700RGWR  [RGW0020A]
U9  TPS70918DBVT  [DBV0005A_N]
U10  TPS70918DBVT  [DBV0005A_N]

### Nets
1P8V_ISO: C38.1 C39.1 TP8.1 U9.5(OUT)
3P3V: R38.2 TP6.1 U7.1(OUT) U7.3(SENSE) U7.20(OUT)
3P3V_ISO: R39.2 TP7.1 U8.1(OUT) U8.3(SENSE) U8.20(OUT)
5V_ISO: R23.2 TP2.1 U6.1(OUT) U6.3(SENSE) U6.20(OUT)
5VDC: C20.1 C21.1 C28.1 C29.1 R25.2 R103.2 T1.2 T2.2 TP5.1 U4.2(VCC) U5.7(VOUT) U7.13(EN) U7.15(IN) U7.16(IN)
+12VDC: C22.1 C23.1 D2.1(K) R24.2 R26.2 R40.2 TP4.1 U5.1(VIN)
+12VDC_IN: C24.1 D2.2(A) J5.1
A1P8V_ISO: C42.1 C43.1 TP9.1 U10.5(OUT)
AGND_ISO: C13.2(-) C14.2 C15.2 C16.2 C17.2 C18.1 C19.2 C25.2 C26.1 C30.2 C31.2 C33.2 C35.1 C36.2 C37.2 C38.2 C39.2 C40.2 C41.2 C42.2 C43.2 R27.1 R28.1 R29.1 R30.1 R32.1 R33.1 R35.1 R37.1 R42.1 R44.1 R46.1 R48.1 R50.1 R52.1 R54.1 R56.1 T1.5 T2.5 U6.7(GND) U6.21(PAD) U8.7(GND) U8.21(PAD) U9.2(GND) U10.2(GND)
GND: C21.2 C22.2 C23.2 C24.2 C27.2 C28.2 C29.2 C32.2 C34.1 D4.1(K) J5.2 R34.1 R36.1 R41.1 R43.1 R45.1 R47.1 R49.1 R51.1 R53.1 R55.1 R104.1 U4.4(GND) U5.4(GND) U5.8(EP) U7.7(GND) U7.21(PAD)
LDO_IN_ISO: C15.1 C16.1 C19.1 C30.1 C31.1 C36.1 C37.1 C40.1 C41.1 J4.2 R22.2 TP10.1 TP11.1 U6.13(EN) U6.15(IN) U6.16(IN) U8.13(EN) U8.15(IN) U8.16(IN) U9.1(IN) U10.1(IN)
FB: C20.2 R25.1 R31.2 U5.6(FB)
TX1: T1.1 T2.1 U4.3(D2)
TX3: T1.3 T2.3 U4.1(D1)
TX4: D3.2(A) T1.4 T2.4
TX6: D1.2(A) T1.6 T2.6
NetC13_1: C13.1(+) C14.1 C17.1 C18.2 D1.1(K) D3.1(K) J4.1 R22.1 TP3.1
NetC25_1: C25.1 R23.1
NetC26_2: C26.2 U6.14(NR)
NetC27_1: C27.1 U5.5(SS)
NetC32_1: C32.1 R38.1
NetC33_1: C33.1 R39.1
NetC34_2: C34.2 U7.14(NR)
NetC35_2: C35.2 U8.14(NR)
NetD4_2: D4.2(A) R40.1
NetR24_1: R24.1 R34.2 U5.3(EN)
NetR26_1: R26.1 U5.2(RON)
NetR27_2: R27.2 U6.4(6P4V2)
NetR28_2: R28.2 U6.5(6P4V1)
NetR29_2: R29.2 U6.6(3P2V)
NetR30_2: R30.2 U6.8(1P6V)
NetR31_1: R31.1 R36.2
NetR32_2: R32.2 U6.9(0P8V)
NetR33_2: R33.2 U6.10(0P4V)
NetR35_2: R35.2 U6.11(0P2V)
NetR37_2: R37.2 U6.12(0P1V)
NetR41_2: R41.2 U7.4(6P4V2)
NetR42_2: R42.2 U8.4(6P4V2)
NetR43_2: R43.2 U7.5(6P4V1)
NetR44_2: R44.2 U8.5(6P4V1)
NetR45_2: R45.2 U7.6(3P2V)
NetR46_2: R46.2 U8.6(3P2V)
NetR47_2: R47.2 U7.8(1P6V)
NetR48_2: R48.2 U8.8(1P6V)
NetR49_2: R49.2 U7.9(0P8V)
NetR50_2: R50.2 U8.9(0P8V)
NetR51_2: R51.2 U7.10(0P4V)
NetR52_2: R52.2 U8.10(0P4V)
NetR53_2: R53.2 U7.11(0P2V)
NetR54_2: R54.2 U8.11(0P2V)
NetR55_2: R55.2 U7.12(0P1V)
NetR56_2: R56.2 U8.12(0P1V)
NetR103_1: R103.1 U4.5(EN)
NetR104_2: R104.2 U4.6(CLK)

Not connected (* = marked no-connect by the designer): U6 2(NC)* 17(NC)* 18(NC)* 19(NC)*; U7 2(NC)* 17(NC)* 18(NC)* 19(NC)*; U8 2(NC)* 17(NC)* 18(NC)* 19(NC)*; U9 3(EN)* 4(NC); U10 3(EN)* 4(NC)

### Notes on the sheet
- (near TP2) ( +5.2 V )
- (near TP5) ( +5.6 V )
- NON-ISOLATED POWER RAIL
- ISOLATED POWER RAIL

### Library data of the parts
C13 = 293D107X9020E2TE3: 100µF ±10% Molded Tantalum Capacitors 20V 2917 (7343 Metric) 35 mOhm; Manufacturer: AVX Corporation; Polarized: Y; Value: 100uF; U/M: EA; Cap_F: 0.0001; Tolerance_%: 10; Value1: 0.5 ohm; VDC_V: 20; ESR_ohm: 0.5; IRMS_A: 0.57; TaMin_C: -55; TaMax_C: 125; Cap_Case: E; AEC Category: Q200
C14 C24 = C3216X7R1E106M160AE: CAP, CERM, 10 µF, 25 V, +/- 20%, X7R, 1206_190; Manufacturer: TDK; Polarized: N; CompType: Capacitor; Value: 10uF; U/M: EA; Cap_F: 0.00001; Tolerance_%: 20; Value1: Unknown; VDC_V: 25; Value2: 25V; TaMin_C: -55; TaMax_C: 125; Cap_Case: 1206; AEC Category: Q200
C15 C25 C28 C30 C32 C33 = C3216X5R1E476M160AC: CAP, CERM, 47 µF, 25 V, +/- 20%, X5R, 1206_190; Manufacturer: TDK; Polarized: N; CompType: Capacitor; Value: 47uF; U/M: EA; Cap_F: 0.000047; Tolerance_%: 20; Value1: Unknown; VDC_V: 25; Value2: 25V; TaMin_C: -55; TaMax_C: 85; Cap_Case: 1206; AEC Category: Q200
C16 C29 C31 = GRM1885C1H102FA01J: CAP, CERM, 1000 pF, 50 V, +/- 1%, C0G/NP0, 0603; Manufacturer: MuRata; Polarized: N; CompType: Capacitor; Value: 1000pF; U/M: EA; Cap_F: 0.000000001; Tolerance_%: 1; Value1: Unknown; VDC_V: 50; Value2: 50V; TaMin_C: -55; TaMax_C: 125; AEC Category: Q200
C17 = GRM188R71E105KA12D: CAP, CERM, 1 µF, 25 V, +/- 10%, X7R, 0603; Manufacturer: MuRata; Polarized: N; CompType: Capacitor; Value: 1uF; U/M: EA; Cap_F: 0.000001; Tolerance_%: 10; Value1: Unknown; VDC_V: 25; Value2: 25V; TaMin_C: -55; TaMax_C: 125
C18 = GRM155R71C104KA88D: as C2 on sheet TIDA-01035_CONNECTOR
C19 = GRM21BR71A106KE51L: as C1 on sheet TIDA-01035_CONNECTOR
C20 = 08055C223KAT2A: CAP, CERM, 0.022uF, 50V, +/-10%, X7R, 0805; Manufacturer: AVX; Polarized: N; CompType: Capacitor; U/M: EA; Cap_F: 0.000000022; Tolerance_%: 10; ESR_Ohm: 0.052; Value1: 0.052 ohm; VDC_V: 50; TaMin_C: -55; TaMax_C: 125; Cap_Case: 0805
C21 = C3225X5R1A226M: CAP, CERM, 22uF, 10V, +/-20%, X5R, 1210; Manufacturer: TDK; Polarized: N; CompType: Capacitor; U/M: EA; Cap_F: 0.000022; Tolerance_%: 20; ESR_Ohm: 0.002; Value1: 0.002 ohm; VDC_V: 10; IRMS_A: 3.2; TaMin_C: -55; TaMax_C: 85
C22 C23 = UMK325AB7106KM-T: 10µF ±10% 50V Ceramic Capacitor X7R 1210 (3225 Metric); Manufacturer: Kemet; Polarized: N; Value: 10uF; U/M: EA; Cap_F: 0.00001; Tolerance_%: 10; Value1: Unknown; VDC_V: 50; TaMin_C: -55; TaMax_C: 125; Cap_Case: 1210; AEC Category: Q200
C26 C34 C35 = GRM188R71E105KA12D: CAP, CERM, 1 µF, 25 V, +/- 10%, X7R, 0603; Manufacturer: MuRata; Polarized: N; CompType: Capacitor; Value: 1uF; U/M: EA; Cap_F: 0.000001; Tolerance_%: 10; Value1: Unknown; VDC_V: 25; Value2: 25V; TaMin_C: -55; TaMax_C: 125; AEC Category: Q200
C27 = C0603C103J5RACTU: CAP, CERM, 0.01uF, 50V, +/-5%, X7R, 0603; Manufacturer: Kemet; Polarized: N; CompType: Capacitor; U/M: EA; Cap_F: 0.00000001; Tolerance_%: 5; Value1: Unknown; VDC_V: 50; TaMin_C: -55; TaMax_C: 125
C36 C40 = 08055C105KAT2A: CAP, CERM, 1uF, 50V, +/-10%, X7R, 0805; Manufacturer: AVX; Polarized: N; CompType: Capacitor; U/M: EA; Cap_F: 0.000001; Tolerance_%: 10; Value1: Unknown; VDC_V: 50; TaMin_C: -55; TaMax_C: 125
C37 C39 C41 C43 = C0603C104K5RACTU: CAP, CERM, 0.1uF, 50V, +/-10%, X7R, 0603; Manufacturer: Kemet; Polarized: N; CompType: Capacitor; U/M: EA; Cap_F: 0.0000001; Tolerance_%: 10; Value1: Unknown; VDC_V: 50; TaMin_C: -55; TaMax_C: 125
C38 C42 = 0805YD106MAT2A: CAP, CERM, 10uF, 16V, +/-20%, X5R, 0805; Manufacturer: AVX; Polarized: N; CompType: Capacitor; U/M: EA; Cap_F: 0.00001; Tolerance_%: 20; Value1: Unknown; VDC_V: 16; TaMin_C: -55; TaMax_C: 85
D1 D3 = MBR0520LT1G: Diode, Schottky, 20 V, 0.5 A, SOD-123; Manufacturer: ON Semiconductor; U/M: EA; Vf_V: 0.385; Value: 20V; Value1: 0.5A; Value2: 0.385V; Io_A: 0.5; Vr_V: 20; TJmax_C: 125; RJC_CperW: 150; AEC Category: Q101
D2 = MBRS4201T3G: Diode, Schottky, 200V, 4A, SMC; Manufacturer: ON Semiconductor; Io_A: 4
D4 = 150060RS75000: LED, Red, SMD; Manufacturer: Wurth Elektronik; Type: AlInGaP; Vf_V: 2; Value2: 2V; Io_A: 0.03; Vr_V: 5; Tjmax_C: 85; Power_TotalModule: 0.072; Value1: 0.072W; Angle: 140; U/M: EA
J4 = 61300211121: as J2 on sheet TIDA-01035_CONNECTOR
J5 = 691213510002: 2 Position Wire to Board Terminal Block Horizontal with Board 0.197" (5.00mm) Through Hole; Manufacturer: Keystone Electronics; ComponentLink1 Description: Manufacturer; ComponentLink2 Description: Datasheet; NoPins: 2
R22 = CRCW12060000Z0EA: RES, 0, 5%, 0.25 W, 1206; Manufacturer: Vishay-Dale; CompType: Resistor; Value: 0; Value_Code: 0000; Tolerance_%: 5; Power_W: 0.25; Value2: 0.25W; VDC_V: 200; TempCo: 200 ppm/C; EIA_Code: E24; U/M: EA; AEC Category: Q200
R23 R38 R39 = ERJ-3RSFR10V: RES, 0.1, 1%, 0.1 W, 0603; Manufacturer: Panasonic; CompType: Resistor; Value: 0.1; Value_Code: R100; Tolerance_%: 1; Value2: 0.1W; TempCo: 300 ppm/C; EIA_Code: E96; U/M: EA; AEC Category: Q200
R24 = ERJ-6ENF1183V: RES, 118 k, 1%, 0.125 W, 0805; Manufacturer: Panasonic; CompType: Resistor; Value: 118k; Res_ohm: 118000; Tolerance_%: 1; Power_W: 0.125; Value2: 0.125W; TempCo: 100 ppm/C; EIA_Code: E96; U/M: EA; SizeArea_mm2: 2.5; SizeX_mm: 2; SizeY_mm: 1.25; SizeZ_mm: 1.45; AEC Category: Q200
R25 = RT0805BRD075K62L: RES, 5.62 k, 0.1%, 0.125 W, 0805; Manufacturer: Yageo America; CompType: Resistor; Value: 5.62k; Res_ohm: 5620; Value_Code: 5k62; Tolerance_%: 0.1; Power_W: 0.125; Value2: 0.125W; VDC_V: 150; TempCo: 25 ppm/C; EIA_Code: E192; U/M: EA; AEC Category: Q200
R26 = CRCW0805249KFKEA: RES, 249k ohm, 1%, 0.125W, 0805; Manufacturer: Vishay-Dale; CompType: Resistor; Res_ohm: 249000; Tolerance_%: 1; Power_W: 0.125; VDC_V: 150; TempCo: 100 ppm/C; EIA_Code: E96; U/M: EA
R27-R30 R32 R33 R35 R37 R41-R56 = ERJ-2GE0R00X: as R1 on sheet TIDA-01035_CONNECTOR
R31 = RR1220P-5490-D-M: RES, 549, 0.5%, 0.1 W, 0805; Manufacturer: Susumu Co Ltd; CompType: Resistor; Value: 549; Value_Code: 549R; Tolerance_%: 0.5; Power_W: 0.1; Value2: 0.1W; VDC_V: 100; TempCo: 25 ppm/C; EIA_Code: E192; U/M: EA; AEC Category: Q200; SizeArea_mm2: 2.5; SizeX_mm: 2; SizeY_mm: 1.25; SizeZ_mm: 1.45
R34 = CRCW080520K5FKEA: RES, 20.5 k, 1%, 0.125 W, 0805; Manufacturer: Vishay-Dale; CompType: Resistor; Value: 20.5k; Res_ohm: 20500; Value_Code: 20k5; Tolerance_%: 1; Power_W: 0.125; Value2: 0.125W; VDC_V: 150; TempCo: 100 ppm/C; EIA_Code: E96; U/M: EA; AEC Category: Q200
R36 = RR1220P-3920-D-M: RES, 392, 0.5%, 0.1 W, 0805; Manufacturer: Susumu Co Ltd; CompType: Resistor; Value: 392; Value_Code: 392R; Tolerance_%: 0.5; Power_W: 0.1; Value2: 0.1W; VDC_V: 100; TempCo: 25 ppm/C; EIA_Code: E192; U/M: EA; AEC Category: Q200; SizeArea_mm2: 2.5; SizeX_mm: 2; SizeY_mm: 1.25; SizeZ_mm: 1.45
R40 = CRCW06031K20JNEA: RES, 1.2 k, 5%, 0.1 W, 0603; Manufacturer: Vishay-Dale; CompType: Resistor; Value: 1.2k; Res_ohm: 1200; Value_Code: 1k20; Tolerance_%: 5; Power_W: 0.1; Value2: 0.1W; VDC_V: 75; TempCo: 200 ppm/C; EIA_Code: E24; U/M: EA; AEC Category: Q200
R103 R104 = CRCW06030000Z0EA: RES, 0, 5%, 0.1 W, 0603; Manufacturer: Vishay-Dale; CompType: Resistor; Value: 0; Value_Code: 0000; Tolerance_%: 5; Power_W: 0.1; Value2: 0.1W; VDC_V: 75; TempCo: 200 ppm/C; EIA_Code: E24; U/M: EA; AEC Category: Q200
T1 = 750313734: Transformer, 340 uH, TH; Manufacturer: Wurth Elektronik; SymbolCreator: Altium; Value: 340uH; Lp: 340; DCR_ohm: 0.419
T2 = 750315240: Transformer, 110 uH, SMT; Manufacturer: Wurth Elektronik; SymbolCreator: Altium; Value: 110uH; Lp: 110; DCR_ohm: 0.15
TP2-TP11 = 5015: Test Point, Miniature, SMT; Manufacturer: Keystone; CompType: Test Point Loop
U4 = SN6505ADBVR: LOW-NOISE 1A TRANSFORMER DRIVERS FOR ISOLATED POWER SUPPLIES, DBV0006A; Alternate PartNumber: SN6505ADBVT; Manufacturer: Texas Instruments; SymbolCreator: Altium; CompType: IC; U/M: EA
U5 = LMZ14203TZ-ADJ/NOPB: 3A SIMPLE SWITCHER® Power Module with 42V Maximum Input Voltage, 7-pin TO-PMOD, Pb-Free; Manufacturer: Texas Instruments; PackageTopMarking: NSUZXYTTE#*LMZ14203*TZ-ADJ; PowerWise: Y
U6-U8 = TPS7A4700RGWR: 36-V, 1-A, 4.17-μVRMS, RF LDO Voltage Regulator, RGW0020A; Alternate PartNumber: TPS7A4700RGWT; Manufacturer: Texas Instruments; SymbolCreator: a0412235; CompType: IC; U/M: EA
U9 U10 = TPS70933DBVT: IC REG LDO 1.8V 0.15A SOT23-5; Alternate Manufacturer: None; Manufacturer: Texas Instruments; SymbolCreator: a0411947; U/M: EA

## Sheet TIDA-01035_DATA_ISOLATION.SchDoc
size 431 x 279 mm; Date: Not shown in title block; ApprovedBy: Not shown in title block; CheckedBy: Not shown in title block; Author: Not shown in title block; CompanyName: Not shown in title block; Engineer: Not shown in title block; Organization: Not shown in title block; Address1: Not shown in title block; Address2: Not shown in title block; Address3: Not shown in title block; Address4: Not shown in title block; DocumentNumber: 1; Revision: Use project parameter SCH_Rev; SheetNumber: 4; SheetTotal: 6; PageSetup: Record=PageOptions¦CenterHorizontal=True¦CenterVertical=True¦PrintScale=1.00¦XCorrection=1.00¦YCorrection=1.00¦PrintKind=0¦BorderSize=5000000¦LeftOffset=0¦BottomOffset=0¦Orientation=2¦PaperLength=1000¦PaperWidth=1000¦Scale=100¦PaperSource=15¦PrintQuality=600¦MediaType=1¦DitherType=10¦PaperKind=Letter¦PrintScaleMode=1
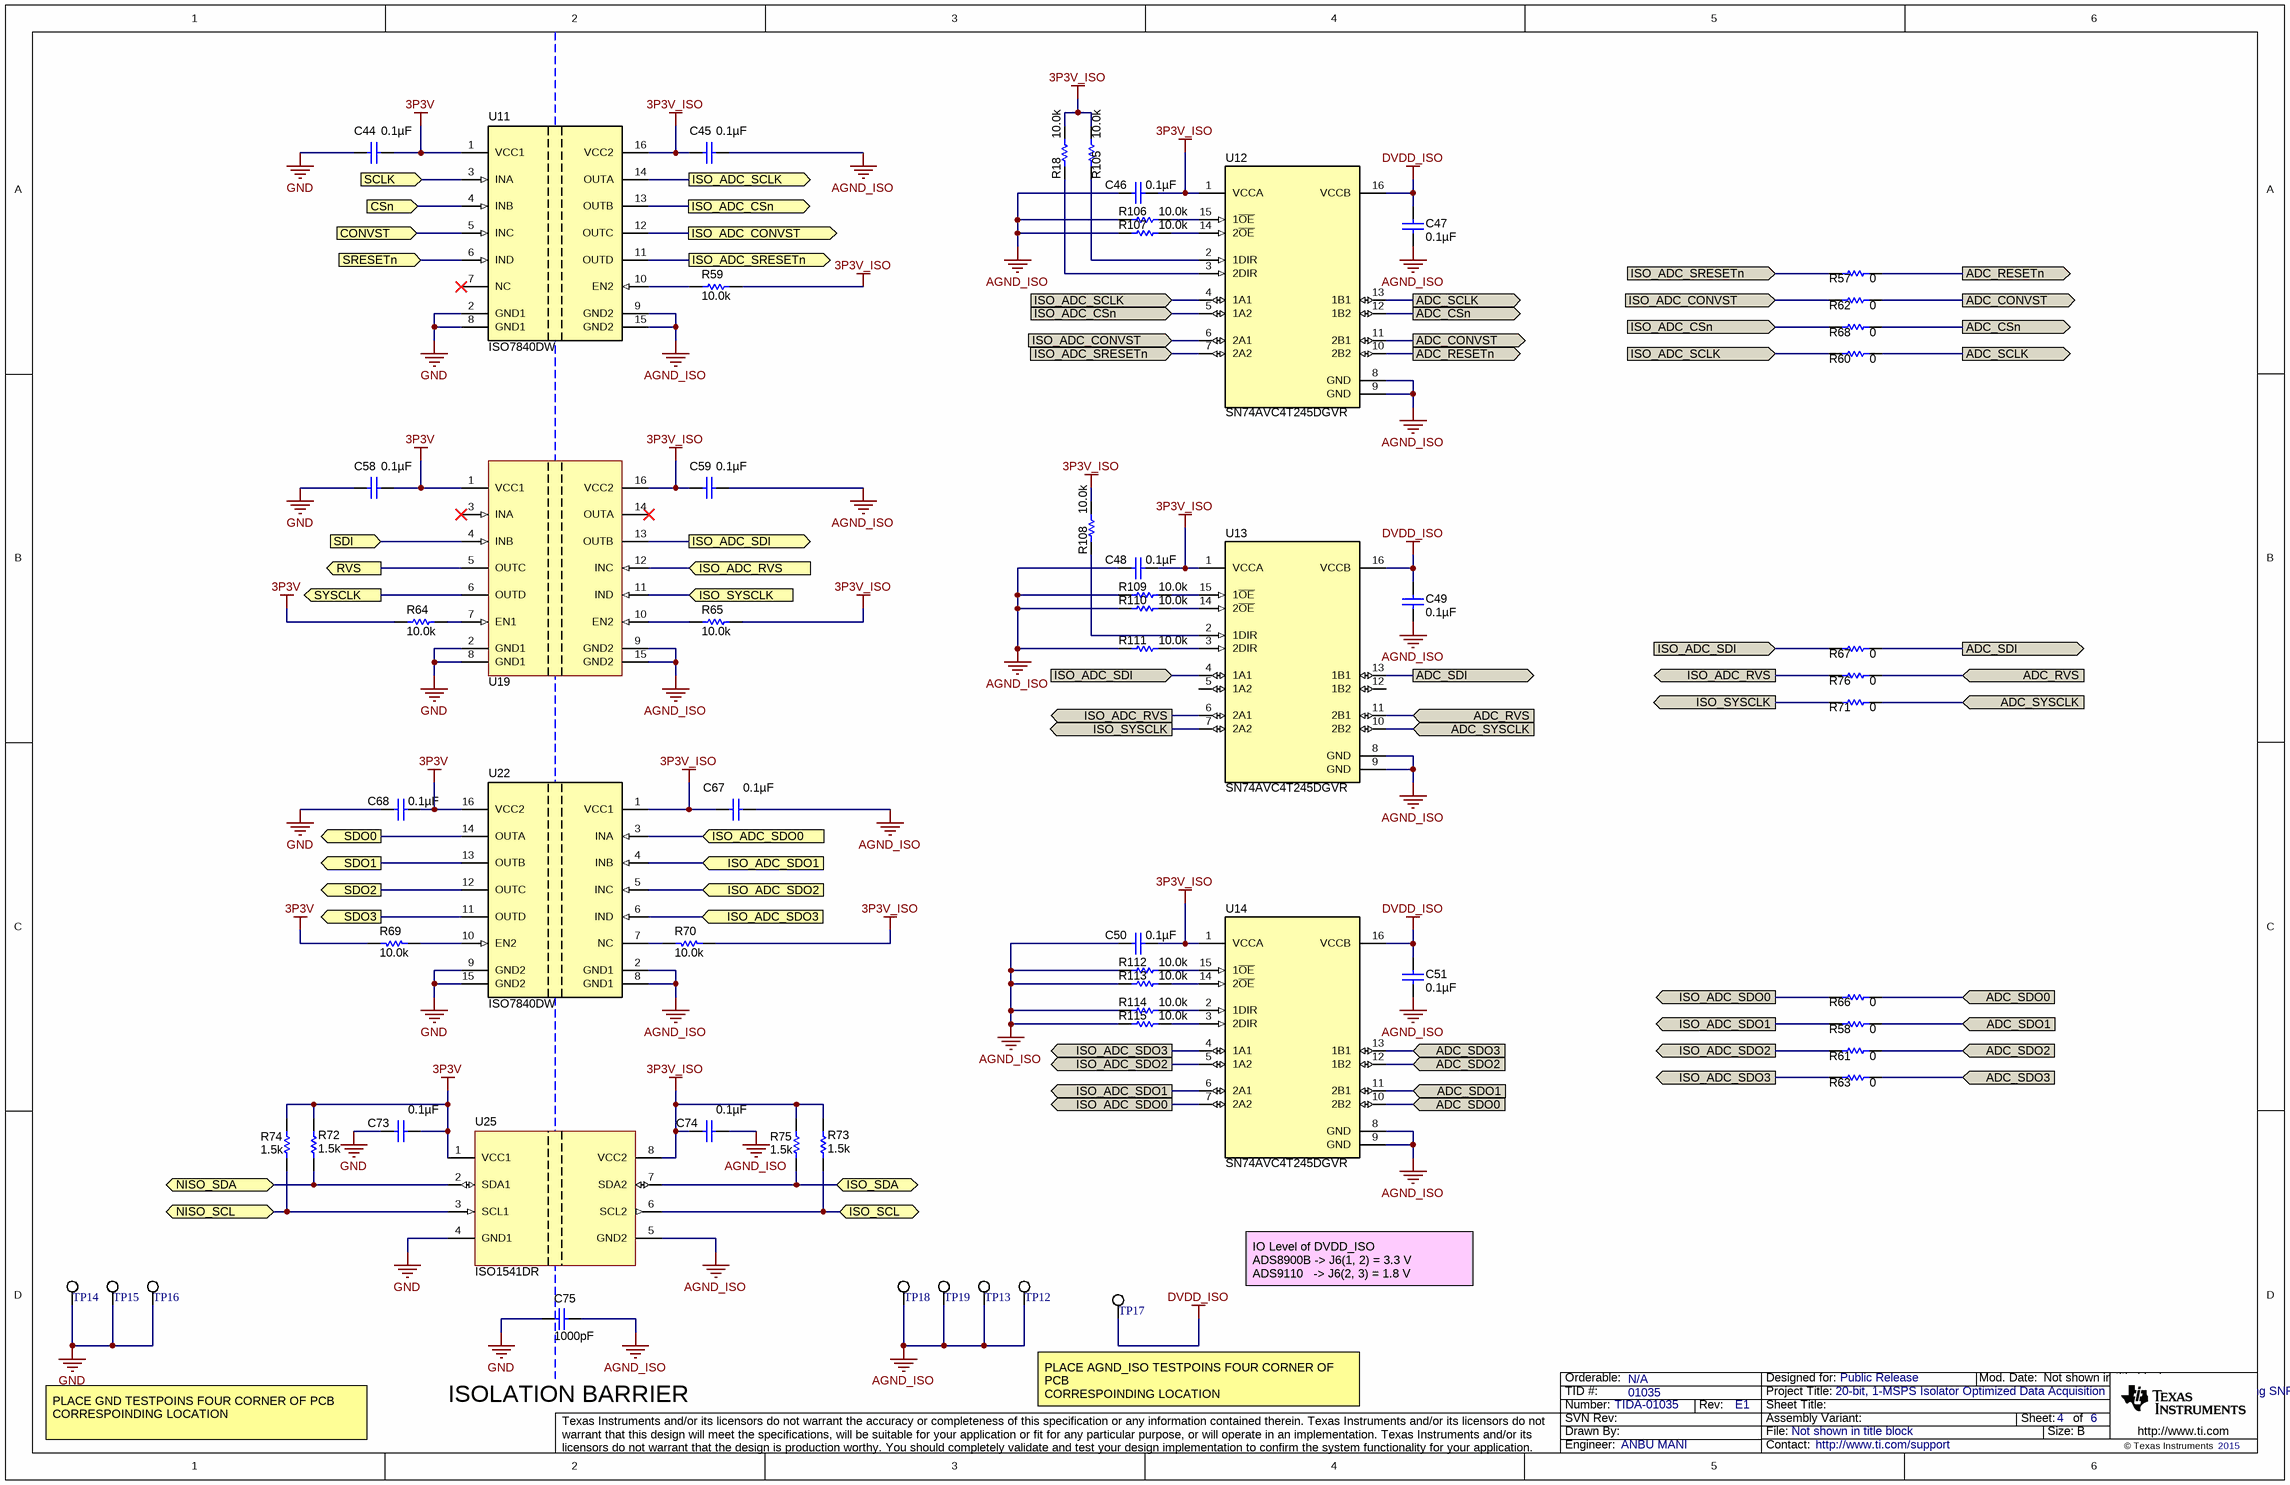
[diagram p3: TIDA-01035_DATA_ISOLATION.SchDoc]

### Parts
C44  ValueDisplayed: 0.1µF  [0402]  (hidden comment: GRM155R71C104KA88D)
C45  ValueDisplayed: 0.1µF  [0402]  (hidden comment: GRM155R71C104KA88D)
C46  ValueDisplayed: 0.1µF  [0402]  (hidden comment: GRM155R71C104KA88D)
C47  ValueDisplayed: 0.1µF  [0402]  (hidden comment: GRM155R71C104KA88D)
C48  ValueDisplayed: 0.1µF  [0402]  (hidden comment: GRM155R71C104KA88D)
C49  ValueDisplayed: 0.1µF  [0402]  (hidden comment: GRM155R71C104KA88D)
C50  ValueDisplayed: 0.1µF  [0402]  (hidden comment: GRM155R71C104KA88D)
C51  ValueDisplayed: 0.1µF  [0402]  (hidden comment: GRM155R71C104KA88D)
C58  ValueDisplayed: 0.1µF  [0402]  (hidden comment: GRM155R71C104KA88D)
C59  ValueDisplayed: 0.1µF  [0402]  (hidden comment: GRM155R71C104KA88D)
C67  ValueDisplayed: 0.1µF  [0402]  (hidden comment: GRM155R71C104KA88D)
C68  ValueDisplayed: 0.1µF  [0402]  (hidden comment: GRM155R71C104KA88D)
C73  ValueDisplayed: 0.1µF  [0402]  (hidden comment: GRM155R71C104KA88D)
C74  ValueDisplayed: 0.1µF  [0402]  (hidden comment: GRM155R71C104KA88D)
C75  ValueDisplayed: 1000pF  [1206_190]  (hidden comment: 202R18W102KV4E)
R18  ValueDisplayed: 10.0k  [0402]  (hidden comment: ERJ-2RKF1002X)
R57  ValueDisplayed: 0  [0201]  (hidden comment: ERJ-1GN0R00C)
R58  ValueDisplayed: 0  [0201]  (hidden comment: ERJ-1GN0R00C)
R59  ValueDisplayed: 10.0k  [0402]  (hidden comment: ERJ-2RKF1002X)
R60  ValueDisplayed: 0  [0201]  (hidden comment: ERJ-1GN0R00C)
R61  ValueDisplayed: 0  [0201]  (hidden comment: ERJ-1GN0R00C)
R62  ValueDisplayed: 0  [0201]  (hidden comment: ERJ-1GN0R00C)
R63  ValueDisplayed: 0  [0201]  (hidden comment: ERJ-1GN0R00C)
R64  ValueDisplayed: 10.0k  [0402]  (hidden comment: ERJ-2RKF1002X)
R65  ValueDisplayed: 10.0k  [0402]  (hidden comment: ERJ-2RKF1002X)
R66  ValueDisplayed: 0  [0201]  (hidden comment: ERJ-1GN0R00C)
R67  ValueDisplayed: 0  [0201]  (hidden comment: ERJ-1GN0R00C)
R68  ValueDisplayed: 0  [0201]  (hidden comment: ERJ-1GN0R00C)
R69  ValueDisplayed: 10.0k  [0402]  (hidden comment: ERJ-2RKF1002X)
R70  ValueDisplayed: 10.0k  [0402]  (hidden comment: ERJ-2RKF1002X)
R71  ValueDisplayed: 0  [0201]  (hidden comment: ERJ-1GN0R00C)
R72  ValueDisplayed: 1.5k  [0603]  (hidden comment: CRCW06031K50JNEA)
R73  ValueDisplayed: 1.5k  [0603]  (hidden comment: CRCW06031K50JNEA)
R74  ValueDisplayed: 1.5k  [0603]  (hidden comment: CRCW06031K50JNEA)
R75  ValueDisplayed: 1.5k  [0603]  (hidden comment: CRCW06031K50JNEA)
R76  ValueDisplayed: 0  [0201]  (hidden comment: ERJ-1GN0R00C)
R105  ValueDisplayed: 10.0k  [0402]  (hidden comment: ERJ-2RKF1002X)
R106  ValueDisplayed: 10.0k  [0402]  (hidden comment: ERJ-2RKF1002X)
R107  ValueDisplayed: 10.0k  [0402]  (hidden comment: ERJ-2RKF1002X)
R108  ValueDisplayed: 10.0k  [0402]  (hidden comment: ERJ-2RKF1002X)
R109  ValueDisplayed: 10.0k  [0402]  (hidden comment: ERJ-2RKF1002X)
R110  ValueDisplayed: 10.0k  [0402]  (hidden comment: ERJ-2RKF1002X)
R111  ValueDisplayed: 10.0k  [0402]  (hidden comment: ERJ-2RKF1002X)
R112  ValueDisplayed: 10.0k  [0402]  (hidden comment: ERJ-2RKF1002X)
R113  ValueDisplayed: 10.0k  [0402]  (hidden comment: ERJ-2RKF1002X)
R114  ValueDisplayed: 10.0k  [0402]  (hidden comment: ERJ-2RKF1002X)
R115  ValueDisplayed: 10.0k  [0402]  (hidden comment: ERJ-2RKF1002X)
TP12  5015  [Testpoint_Keystone_Miniature]  (value not drawn)
TP13  5015  [Testpoint_Keystone_Miniature]  (value not drawn)
TP14  5015  [Testpoint_Keystone_Miniature]  (value not drawn)
TP15  5015  [Testpoint_Keystone_Miniature]  (value not drawn)
TP16  5015  [Testpoint_Keystone_Miniature]  (value not drawn)
TP17  5015  [Testpoint_Keystone_Miniature]  (value not drawn)
TP18  5015  [Testpoint_Keystone_Miniature]  (value not drawn)
TP19  5015  [Testpoint_Keystone_Miniature]  (value not drawn)
U11  ISO7840DW  [DW0016B_N]
U12  SN74AVC4T245DGVR  [DGV0016A_N]
U13  SN74AVC4T245DGVR  [DGV0016A_N]
U14  SN74AVC4T245DGVR  [DGV0016A_N]
U19  ISO7842DWR  [DW0016B_N]  (value not drawn)
U22  ISO7840DW  [DW0016B_N]
U25  ISO1541DR  [D0008A_N]

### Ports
ADC_CONVST (out), ADC_CSn (out), ADC_RESETn (out), ADC_RVS (in), ADC_SCLK (out), ADC_SDI (out), ADC_SDO0 (in), ADC_SDO1 (in), ADC_SDO2 (in), ADC_SDO3 (in), ADC_SYSCLK (in), CONVST (in), CSn (in), ISO_ADC_CONVST (in), ISO_ADC_CONVST (out), ISO_ADC_CSn (in), ISO_ADC_CSn (out), ISO_ADC_RVS (in), ISO_ADC_RVS (out), ISO_ADC_SCLK (in), ISO_ADC_SCLK (out), ISO_ADC_SDI (in), ISO_ADC_SDI (out), ISO_ADC_SDO0 (in), ISO_ADC_SDO0 (out), ISO_ADC_SDO1 (in), ISO_ADC_SDO1 (out), ISO_ADC_SDO2 (in), ISO_ADC_SDO2 (out), ISO_ADC_SDO3 (in), ISO_ADC_SDO3 (out), ISO_ADC_SRESETn (in), ISO_ADC_SRESETn (out), ISO_SCL (bidir), ISO_SDA (bidir), ISO_SYSCLK (in), ISO_SYSCLK (out), NISO_SCL (bidir), NISO_SDA (bidir), RVS (out), SCLK (in), SDI (in), SDO0 (out), SDO1 (out), SDO2 (out), SDO3 (out), SRESETn (in), SYSCLK (out)

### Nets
3P3V: C44.2 C58.2 C68.1 C73.2 R64.1 R69.2 R72.2 R74.2 U11.1(VCC1) U19.1(VCC1) U22.16(VCC2) U25.1(VCC1)
3P3V_ISO: C45.1 C46.1 C48.1 C50.1 C59.1 C67.2 C74.1 R18.2 R59.2 R65.2 R70.1 R73.2 R75.2 R105.2 R108.2 U11.16(VCC2) U12.1(VCCA) U13.1(VCCA) U14.1(VCCA) U19.16(VCC2) U22.1(VCC1) U25.8(VCC2)
AGND_ISO: C45.2 C46.2 C47.2 C48.2 C49.2 C50.2 C51.2 C59.2 C67.1 C74.2 C75.1 R106.1 R107.1 R109.1 R110.1 R111.1 R112.1 R113.1 R114.1 R115.1 TP12.1 TP13.1 TP18.1 TP19.1 U11.9(GND2) U11.15(GND2) U12.8(GND) U12.9(GND) U13.8(GND) U13.9(GND) U14.8(GND) U14.9(GND) U19.9(GND2) U19.15(GND2) U22.2(GND1) U22.8(GND1) U25.5(GND2)
DVDD_ISO: C47.1 C49.1 C51.1 TP17.1 U12.16(VCCB) U13.16(VCCB) U14.16(VCCB)
GND: C44.1 C58.1 C68.2 C73.1 C75.2 TP14.1 TP15.1 TP16.1 U11.2(GND1) U11.8(GND1) U19.2(GND1) U19.8(GND1) U22.9(GND2) U22.15(GND2) U25.4(GND1)
ADC_CONVST: R62.2 U12.11(2B1) ; port ADC_CONVST
ADC_CSn: R68.2 U12.12(1B2) ; port ADC_CSn
ADC_RESETn: R57.2 U12.10(2B2) ; port ADC_RESETn
ADC_RVS: R76.2 U13.11(2B1) ; port ADC_RVS
ADC_SCLK: R60.2 U12.13(1B1) ; port ADC_SCLK
ADC_SDI: R67.2 U13.13(1B1) ; port ADC_SDI
ADC_SDO0: R66.2 U14.10(2B2) ; port ADC_SDO0
ADC_SDO1: R58.2 U14.11(2B1) ; port ADC_SDO1
ADC_SDO2: R61.2 U14.12(1B2) ; port ADC_SDO2
ADC_SDO3: R63.2 U14.13(1B1) ; port ADC_SDO3
ADC_SYSCLK: R71.2 U13.10(2B2) ; port ADC_SYSCLK
CONVST: U11.5(INC) ; port CONVST
CSn: U11.4(INB) ; port CSn
ISO_ADC_CONVST: R62.1 U11.12(OUTC) U12.6(2A1) ; port ISO_ADC_CONVST
ISO_ADC_CSn: R68.1 U11.13(OUTB) U12.5(1A2) ; port ISO_ADC_CSn
ISO_ADC_RVS: R76.1 U13.6(2A1) U19.12(INC) ; port ISO_ADC_RVS
ISO_ADC_SCLK: R60.1 U11.14(OUTA) U12.4(1A1) ; port ISO_ADC_SCLK
ISO_ADC_SDI: R67.1 U13.4(1A1) U19.13(OUTB) ; port ISO_ADC_SDI
ISO_ADC_SDO0: R66.1 U14.7(2A2) U22.3(INA) ; port ISO_ADC_SDO0
ISO_ADC_SDO1: R58.1 U14.6(2A1) U22.4(INB) ; port ISO_ADC_SDO1
ISO_ADC_SDO2: R61.1 U14.5(1A2) U22.5(INC) ; port ISO_ADC_SDO2
ISO_ADC_SDO3: R63.1 U14.4(1A1) U22.6(IND) ; port ISO_ADC_SDO3
ISO_ADC_SRESETn: R57.1 U11.11(OUTD) U12.7(2A2) ; port ISO_ADC_SRESETn
ISO_SCL: R73.1 U25.6(SCL2) ; port ISO_SCL
ISO_SDA: R75.1 U25.7(SDA2) ; port ISO_SDA
ISO_SYSCLK: R71.1 U13.7(2A2) U19.11(IND) ; port ISO_SYSCLK
NISO_SCL: R74.1 U25.3(SCL1) ; port NISO_SCL
NISO_SDA: R72.1 U25.2(SDA1) ; port NISO_SDA
RVS: U19.5(OUTC) ; port RVS
SCLK: U11.3(INA) ; port SCLK
SDI: U19.4(INB) ; port SDI
SDO0: U22.14(OUTA) ; port SDO0
SDO1: U22.13(OUTB) ; port SDO1
SDO2: U22.12(OUTC) ; port SDO2
SDO3: U22.11(OUTD) ; port SDO3
SRESETn: U11.6(IND) ; port SRESETn
SYSCLK: U19.6(OUTD) ; port SYSCLK
NetR18_1: R18.1 U12.3(2DIR)
NetR59_1: R59.1 U11.10(EN2)
NetR64_2: R64.2 U19.7(EN1)
NetR65_1: R65.1 U19.10(EN2)
NetR69_1: R69.1 U22.10(EN2)
NetR70_2: R70.2 U22.7(NC)
NetR105_1: R105.1 U12.2(1DIR)
NetR106_2: R106.2 U12.15(1~{OE})
NetR107_2: R107.2 U12.14(2~{OE})
NetR108_1: R108.1 U13.2(1DIR)
NetR109_2: R109.2 U13.15(1~{OE})
NetR110_2: R110.2 U13.14(2~{OE})
NetR111_2: R111.2 U13.3(2DIR)
NetR112_2: R112.2 U14.15(1~{OE})
NetR113_2: R113.2 U14.14(2~{OE})
NetR114_2: R114.2 U14.2(1DIR)
NetR115_2: R115.2 U14.3(2DIR)

Not connected (* = marked no-connect by the designer): U11 7(NC)*; U13 5(1A2) 12(1B2); U19 3(INA)* 14(OUTA)*

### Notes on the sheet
- IO Level of DVDD_ISO
  ADS8900B -> J6(1, 2) = 3.3 V
  ADS9110   -> J6(2, 3) = 1.8 V
- PLACE GND TESTPOINS FOUR CORNER OF PCB
  CORRESPOINDING LOCATION
- ISOLATION BARRIER
- PLACE AGND_ISO TESTPOINS FOUR CORNER OF PCB
  CORRESPOINDING LOCATION

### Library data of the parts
C44-C51 C58 C59 C67 C68 C73 C74 = GRM155R71C104KA88D: as C2 on sheet TIDA-01035_CONNECTOR
C75 = 202R18W102KV4E: CAP, CERM, 1000 pF, 2000 V, +/- 10%, X7R, 1206_190; Manufacturer: Johanson Technology; Polarized: N; CompType: Capacitor; Value: 1000pF; U/M: EA; Cap_F: 0.000000001; Tolerance_%: 10; Value1: Unknown; VDC_V: 2000; Value2: 2000V; TaMin_C: -55; TaMax_C: 125; Cap_Case: 1206; AEC Category: Q200
R18 R59 R64 R65 R69 R70 R105-R115 = ERJ-2RKF1002X: RES, 10.0 k, 1%, 0.1 W, 0402; Manufacturer: Panasonic; CompType: Resistor; Value: 10.0k; Res_ohm: 10000; Value_Code: 10k0; Tolerance_%: 1; Power_W: 0.1; Value2: 0.1W; VDC_V: 50; TempCo: 100 ppm/C; EIA_Code: E96; U/M: EA; AEC Category: Q200
R57 R58 R60-R63 R66-R68 R71 R76 = CRCW04020000Z0ED: RES SMD 0.0OHM JUMPER 1/20W 0201; Manufacturer: Panasonic Electronic Components; CompType: Resistor; Value: 0; Value_Code: 0000; Tolerance_%: 5; Value1: 5%; Power_W: 0.063; Value2: 0.05W, 1/20W; VDC_V: 50; TempCo: 200 ppm/C; EIA_Code: E24; U/M: EA; AEC Category: Q200
R72-R75 = CRCW06031K50JNEA: RES, 1.5 k, 5%, 0.1 W, 0603; Manufacturer: Vishay-Dale; CompType: Resistor; Value: 1.5k; Res_ohm: 1500; Value_Code: 1k50; Tolerance_%: 5; Power_W: 0.1; Value2: 0.1W; VDC_V: 75; TempCo: 200 ppm/C; EIA_Code: E24; U/M: EA; AEC Category: Q200
TP12-TP19 = 5015: as TP2 on sheet TIDA-01035_POWER_ISOLATION
U11 U22 = ISO7840DWR: High-Performance, 8000 VPK Reinforced Quad-Channel Digital Isolator, DW0016B; Manufacturer: Texas Instruments; SymbolCreator: a0411947; CompType: IC; U/M: EA
U12-U14 = SN74AVC4T245DGVR: 4-Bit Dual-supply Bus Transceiver with Configurable Voltage Translation and 3-State Outputs, DGV0016A; Manufacturer: Texas Instruments; SymbolCreator: Altium; SizeArea_mm2: 40.96; SizeAreaWB_mm2: 70.56; SizeX_mm: 6.4; SizeZ_mm: 1.2; CompType: IC; U/M: EA
U19 = ISO7842DWR: High-Performance, 8000 VPK Reinforced Quad Channel Digital Isolator, DW0016B; Manufacturer: Texas Instruments; SymbolCreator: Altium; CompType: IC; U/M: EA
U25 = ISO1541DR: Low-Power Bidirectional I2C Isolators, D0008A; Manufacturer: Texas Instruments; SymbolCreator: a0411947; CompType: IC; U/M: EA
